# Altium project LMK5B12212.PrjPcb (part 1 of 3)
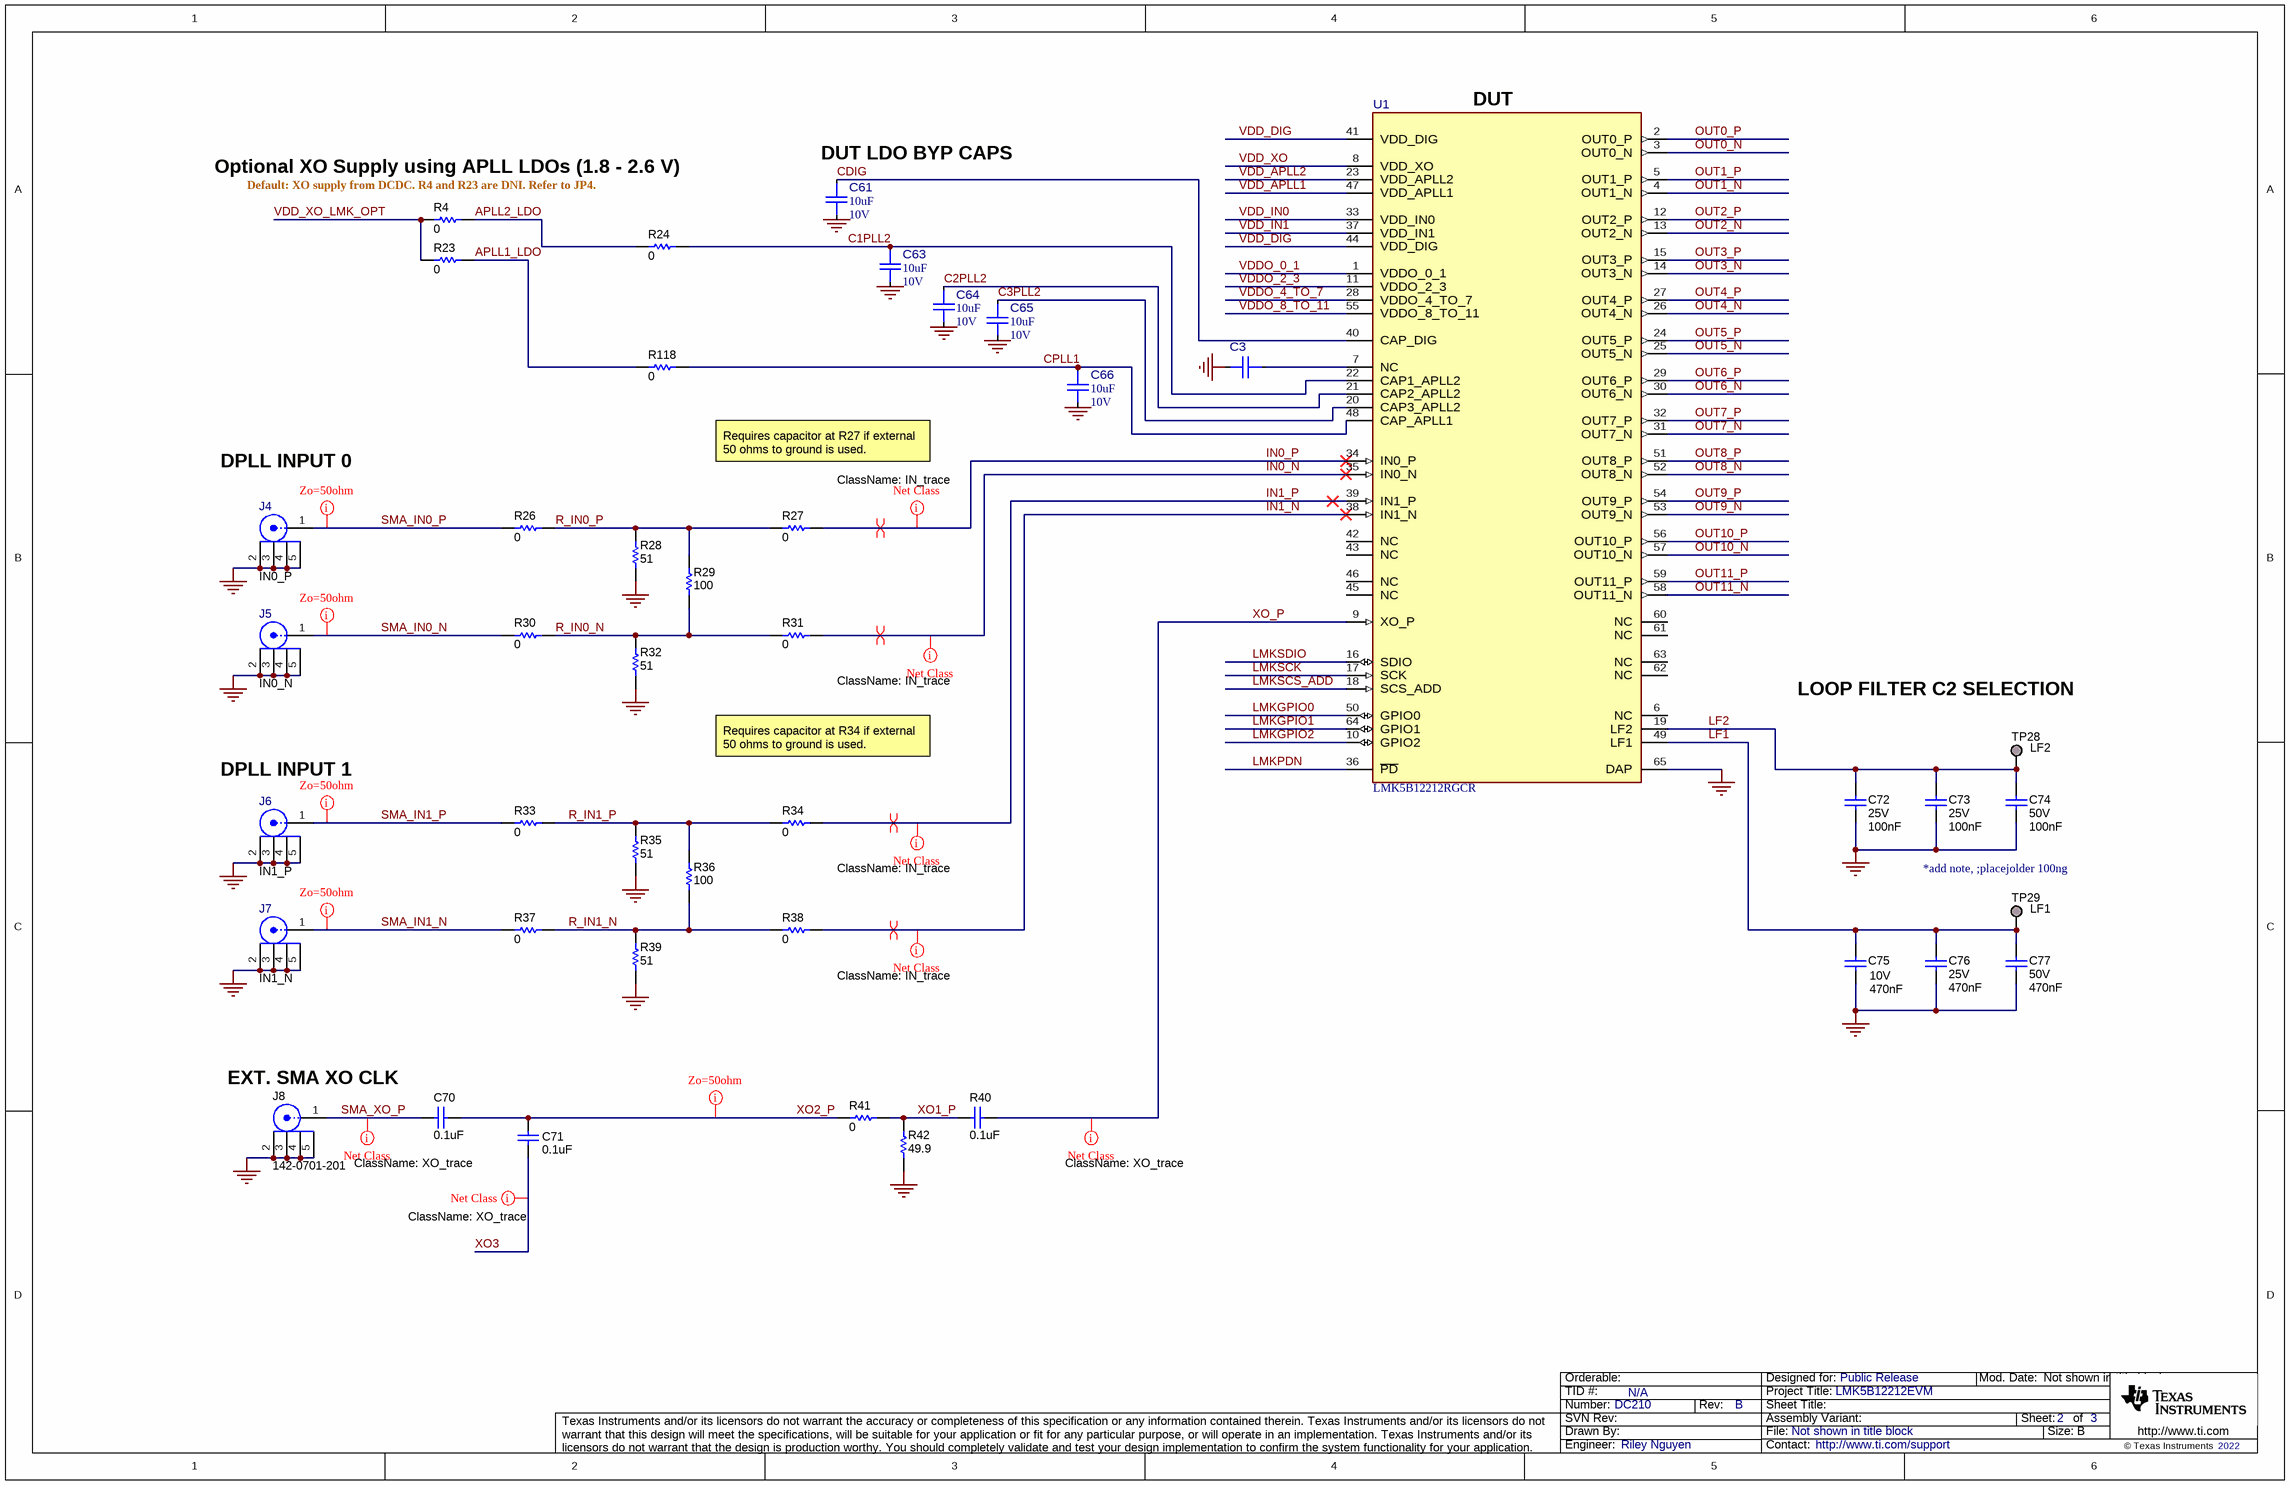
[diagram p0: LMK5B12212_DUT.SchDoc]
CopyrightYear: 2022; PCB_Rev: A; PRJ_Customer: Public Release; PRJ_Engineer: Riley Nguyen; PRJ_Number: DC210; PRJ_Title: LMK5B12212EVM; SCH_Rev: B; TechSupport: http://www.ti.com/support; TID: N/A
11 sheets, 474 parts. Net scope: global (net labels, ports and power ports of the same name join across sheets).
Board file: LMK5B12212_PCB.PcbDoc
Sheets:
  LMK5B12212_DUT.SchDoc
  LMK5B12212_Hardware.SchDoc
  LMK5B12212_Logic.SchDoc
  LMK5B12212_Outputs_A.SchDoc
  LMK5B12212_Outputs_B.SchDoc
  LMK5B12212_Outputs_C.SchDoc
  LMK5B12212_Power.SchDoc
  LMK5B12212_Power_Alternate.SchDoc
  LMK5B12212_PowerDist.SchDoc
  LMK5B12212_USB2ANY.SchDoc
  LMK5B12212_XO.SchDoc

## Sheet LMK5B12212_DUT.SchDoc
size 431 x 279 mm; Date: Not shown in title block; ApprovedBy: Not shown in title block; CheckedBy: Not shown in title block; Author: Not shown in title block; CompanyName: Not shown in title block; Engineer: Not shown in title block; Organization: Not shown in title block; Address1: Not shown in title block; Address2: Not shown in title block; Address3: Not shown in title block; Address4: Not shown in title block; DocumentNumber: 2; Revision: Use project parameter SCH_Rev; SheetNumber: 2; SheetTotal: 3; PageSetup: Record=PageOptions¦CenterHorizontal=True¦CenterVertical=True¦PrintScale=1.00¦XCorrection=1.00¦YCorrection=1.00¦PrintKind=0¦BorderSize=5000000¦LeftOffset=0¦BottomOffset=0¦Orientation=2¦PaperLength=1000¦PaperWidth=1000¦Scale=100¦PaperSource=15¦PrintQuality=600¦MediaType=1¦DitherType=10¦PaperKind=Letter¦PrintScaleMode=1

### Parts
C3  KGM05CR51A106MH  [FP-KGM05CR51A106MH_0402-MFG]  (value not drawn)
C61  ValueDisplayed: 10uF  VDC_V: 10V  [FP-KGM05CR51A106MH_0402-MFG]  (hidden comment: KGM05CR51A106MH)
C63  ValueDisplayed: 10uF  VDC_V: 10V  [FP-KGM05CR51A106MH_0402-MFG]  (hidden comment: KGM05CR51A106MH)
C64  ValueDisplayed: 10uF  VDC_V: 10V  [FP-KGM05CR51A106MH_0402-MFG]  (hidden comment: KGM05CR51A106MH)
C65  ValueDisplayed: 10uF  VDC_V: 10V  [FP-KGM05CR51A106MH_0402-MFG]  (hidden comment: KGM05CR51A106MH)
C66  ValueDisplayed: 10uF  VDC_V: 10V  [FP-KGM05CR51A106MH_0402-MFG]  (hidden comment: KGM05CR51A106MH)
C70  ValueDisplayed: 0.1uF  [0603S]  (hidden comment: C0603C104J3RACTU)
C71  ValueDisplayed: 0.1uF  [0603S]  (hidden comment: C0603C104J3RACTU)
C72  VDC_V: 25V  Cap_F: 100nF  [0603]  (hidden comment: C0603C104J3RACTU)
C73  VDC_V: 25V  ValueDisplayed: 100nF  [0805_150]  (hidden comment: Capacitor)
C74  VDC_V: 50V  ValueDisplayed: 100nF  [1210_280]  (hidden comment: C3225C0G1H104J250AA)
C75  Cap_F: 470nF  VDC_V: 10V  [0603]  (hidden comment: GRM188R71A474KA61D)
C76  VDC_V: 25V  ValueDisplayed: 470nF  [0805_150]  (hidden comment: Capacitor)
C77  VDC_V: 50V  ValueDisplayed: 470nF  [1210_280]  (hidden comment: C3225C0G1H104J250AA)
J4  IN0_P  [FP-CON-SMA-EDGE-S_CONN_JACK-MFG]
J5  IN0_N  [FP-CON-SMA-EDGE-S_CONN_JACK-MFG]
J6  IN1_P  [FP-CON-SMA-EDGE-S_CONN_JACK-MFG]
J7  IN1_N  [FP-CON-SMA-EDGE-S_CONN_JACK-MFG]
J8  142-0701-201  [Johnson_142-0701-20x]
R4  ValueDisplayed: 0  [0603]  (hidden comment: ERJ-3GEY0R00V)
R23  ValueDisplayed: 0  [0603]  (hidden comment: ERJ-3GEY0R00V)
R24  ValueDisplayed: 0  [0402L]  (hidden comment: CRCW04020000Z0EDHP)
R26  ValueDisplayed: 0  [0402L]  (hidden comment: CRCW04020000Z0EDHP)
R27  ValueDisplayed: 0  [0402L]  (hidden comment: CRCW04020000Z0EDHP)
R28  ValueDisplayed: 51  [0402S]  (hidden comment: RC0402JR-0751RL)
R29  ValueDisplayed: 100  [0603S]  (hidden comment: CRCW0603100RFKEA)
R30  ValueDisplayed: 0  [0402L]  (hidden comment: CRCW04020000Z0EDHP)
R31  ValueDisplayed: 0  [0402L]  (hidden comment: CRCW04020000Z0EDHP)
R32  ValueDisplayed: 51  [0402S]  (hidden comment: RC0402JR-0751RL)
R33  ValueDisplayed: 0  [0402L]  (hidden comment: CRCW04020000Z0EDHP)
R34  ValueDisplayed: 0  [0402L]  (hidden comment: CRCW04020000Z0EDHP)
R35  ValueDisplayed: 51  [0402S]  (hidden comment: RC0402JR-0751RL)
R36  ValueDisplayed: 100  [0603S]  (hidden comment: CRCW0603100RFKEA)
R37  ValueDisplayed: 0  [0402L]  (hidden comment: CRCW04020000Z0EDHP)
R38  ValueDisplayed: 0  [0402L]  (hidden comment: CRCW04020000Z0EDHP)
R39  ValueDisplayed: 51  [0402S]  (hidden comment: RC0402JR-0751RL)
R40  ValueDisplayed: 0.1uF  [0603S]  (hidden comment: Capacitor)
R41  value 0  [0603S]  (hidden comment: Resistor)
R42  ValueDisplayed: 49.9  [0603S]  (hidden comment: Resistor)
R118  ValueDisplayed: 0  [0402L]  (hidden comment: CRCW04020000Z0EDHP)
TP28  LF2  [TP_SM_1MM]  (no BOM)
TP29  LF1  [TP_SM_1MM]  (no BOM)
U1  LMK5B12212RGCR  [RGC0064E-MFG]

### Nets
GND: C3.2 C61.2 C63.2 C64.2 C65.2 C66.2 C72.2 C73.1 C74.2 C75.2 C76.1 C77.2 J4.2 J4.3 J4.4 J4.5 J5.2 J5.3 J5.4 J5.5 J6.2 J6.3 J6.4 J6.5 J7.2 J7.3 J7.4 J7.5 J8.2 J8.3 J8.4 J8.5 R28.1 R32.1 R35.1 R39.1 R42.1 U1.65(DAP)
APLL1_LDO: R23.2 R118.1
APLL2_LDO: R4.2 R24.1
C1PLL2: C63.1 R24.2 U1.22(CAP1_APLL2)
C2PLL2: C64.1 U1.21(CAP2_APLL2)
C3PLL2: C65.1 U1.20(CAP3_APLL2)
CDIG: C61.1 U1.40(CAP_DIG)
CPLL1: C66.1 R118.2 U1.48(CAP_APLL1)
IN0_N: R31.2 U1.35(IN0_N)
IN0_P: R27.2 U1.34(IN0_P)
IN1_N: R38.2 U1.38(IN1_N)
IN1_P: R34.2 U1.39(IN1_P)
LF1: C75.1 C76.2 C77.1 TP29.1 U1.49(LF1)
LF2: C72.1 C73.2 C74.1 TP28.1 U1.19(LF2)
LMKGPIO0: U1.50(GPIO0)
LMKGPIO1: U1.64(GPIO1)
LMKGPIO2: U1.10(GPIO2)
LMKPDN: U1.36(~{PD})
LMKSCK: U1.17(SCK)
LMKSCS_ADD: U1.18(SCS_ADD)
LMKSDIO: U1.16(SDIO)
OUT0_N: U1.3(OUT0_N)
OUT0_P: U1.2(OUT0_P)
OUT1_N: U1.4(OUT1_N)
OUT1_P: U1.5(OUT1_P)
OUT2_N: U1.13(OUT2_N)
OUT2_P: U1.12(OUT2_P)
OUT3_N: U1.14(OUT3_N)
OUT3_P: U1.15(OUT3_P)
OUT4_N: U1.26(OUT4_N)
OUT4_P: U1.27(OUT4_P)
OUT5_N: U1.25(OUT5_N)
OUT5_P: U1.24(OUT5_P)
OUT6_N: U1.30(OUT6_N)
OUT6_P: U1.29(OUT6_P)
OUT7_N: U1.31(OUT7_N)
OUT7_P: U1.32(OUT7_P)
OUT8_N: U1.52(OUT8_N)
OUT8_P: U1.51(OUT8_P)
OUT9_N: U1.53(OUT9_N)
OUT9_P: U1.54(OUT9_P)
OUT10_N: U1.57(OUT10_N)
OUT10_P: U1.56(OUT10_P)
OUT11_N: U1.58(OUT11_N)
OUT11_P: U1.59(OUT11_P)
R_IN0_N: R29.1 R30.2 R31.1 R32.2
R_IN0_P: R26.2 R27.1 R28.2 R29.2
R_IN1_N: R36.1 R37.2 R38.1 R39.2
R_IN1_P: R33.2 R34.1 R35.2 R36.2
SMA_IN0_N: J5.1 R30.1
SMA_IN0_P: J4.1 R26.1
SMA_IN1_N: J7.1 R37.1
SMA_IN1_P: J6.1 R33.1
SMA_XO_P: C70.1 J8.1
VDD_APLL1: U1.47(VDD_APLL1)
VDD_APLL2: U1.23(VDD_APLL2)
VDD_DIG: U1.41(VDD_DIG) U1.44(VDD_DIG)
VDD_IN0: U1.33(VDD_IN0)
VDD_IN1: U1.37(VDD_IN1)
VDD_XO: U1.8(VDD_XO)
VDD_XO_LMK_OPT: R4.1 R23.1
VDDO_0_1: U1.1(VDDO_0_1)
VDDO_2_3: U1.11(VDDO_2_3)
VDDO_4_TO_7: U1.28(VDDO_4_TO_7)
VDDO_8_TO_11: U1.55(VDDO_8_TO_11)
XO1_P: R40.1 R41.2 R42.2
XO2_P: C70.2 C71.1 R41.1
XO3: C71.2
XO_P: R40.2 U1.9(XO_P)
NetC3_1: C3.1 U1.7(NC)

Not connected (* = marked no-connect by the designer): U1 6(NC) 42(NC) 43(NC) 45(NC) 46(NC) 60(NC) 61(NC) 62(NC) 63(NC)

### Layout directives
rule Impedance Constraint [Min = 45.00    Max = 55.00    ]: SMA_IN0_N, SMA_IN0_P, SMA_IN1_N, SMA_IN1_P, XO2_P
differential pair: IN0_N, IN0_P, IN1_N, IN1_P
net class XO_trace: SMA_XO_P, XO3, XO_P
net class IN_trace: IN0_N, IN0_P, IN1_N, IN1_P

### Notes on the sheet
- (near U1) DUT
- (near R4) Optional XO Supply using APLL LDOs (1.8 - 2.6 V)
- (near C61) DUT LDO BYP CAPS
- (near R4) Default: XO supply from DCDC. R4 and R23 are DNI. Refer to JP4.
- DPLL INPUT 0
- Requires capacitor at R27 if external 50 ohms to ground is used.
- LOOP FILTER C2 SELECTION
- (near J6) DPLL INPUT 1
- Requires capacitor at R34 if external 50 ohms to ground is used.
- *add note, ;placejolder 100ng
- (near J8) EXT. SMA XO CLK

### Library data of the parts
C3 = CMP-0043010-1: 10 µF ±20% 10V Ceramic Capacitor X5R 0402 (1005 Metric); Manufacturer: KYOCERA AVX; AEC Qualified: No; Cap_F: 10µF; SizeZ_mm: 0.7mm; TempCo: 15%; ValueDisplayed: 10uF; Value: 10µF
C61 C63-C66 = CMP-0043010-1: 10 µF ±20% 10V Ceramic Capacitor X5R 0402 (1005 Metric); Manufacturer: KYOCERA AVX; AEC Qualified: No; Cap_F: 10µF; SizeZ_mm: 0.7mm; TempCo: 15%; Value: 10µF
C70 C71 = CMP-0006856-6: CAP, CERM, 0.1 uF, 25 V, +/- 5%, X7R, 0603; Manufacturer: Kemet; TaMin_C: -55°C; Polarized: N; SizeAreaWB_mm2: 4.68; Value1: Unknown; U/M: EA; Value: 0.1uF; TaMax_C: 125°C; SizeZ_mm: 1; SizeX_mm: 1.6; SizeY_mm: 0.8; Cap_Case: 0603; Value2: 25V; SizeArea_mm2: 1.28; Cap_F: 100nF; AEC Category: Q200
C72 = CMP-0006856-6: CAP, CERM, 0.1 uF, 25 V, +/- 5%, X7R, 0603; Manufacturer: Kemet; Polarized: N; TaMax_C: 125°C; TaMin_C: -55°C; Value: 0.1uF; Value1: Unknown; U/M: EA; AEC Category: Q200; SizeArea_mm2: 1.28; SizeAreaWB_mm2: 4.68; SizeX_mm: 1.6; SizeY_mm: 0.8; SizeZ_mm: 1
C73 C76 = CMP-0078743-1: CAP, CERM, 0.047 µF, 25 V,+/- 5%, C0G/NP0, AEC-Q200 Grade 1, 0805; Manufacturer: Kemet; PartNumber: C0805C473J3GACTU; Polarized: N; TaMax_C: 125°C; TaMin_C: -55°C; Cap_F: 47nF; Value: 0.047uF; U/M: EA; SizeArea_mm2: 2.5; SizeAreaWB_mm2: 6.75; SizeX_mm: 2; SizeY_mm: 1.25; SizeZ_mm: 1.5; AEC Category: Q200; AEC Qualified: Y; AEC Grade: 1; Green_REACh: Incomplete; Green_Lifecycle: Not Set
C74 = CMP-0081101-1: CAP, CERM, 0.1 µF, 50 V,+/- 5%, C0G/NP0, 1210; Manufacturer: TDK; TaMin_C: -55°C; Polarized: N; SizeAreaWB_mm2: 14.7; U/M: EA; Value: 0.1uF; TaMax_C: 125°C; SizeZ_mm: 2.8; SizeX_mm: 3.2; SizeY_mm: 2.5; Cap_Case: 1210; SizeArea_mm2: 8; AEC Category: Q200; Green_Lifecycle: Active; Green_REACh: Incomplete
C75 = CMP-0007373-4: CAP, CERM, 0.47 uF, 10 V, +/- 10%, X7R, 0603; Manufacturer: MuRata; Polarized: N; Value: 0.47uF; U/M: EA; Value1: Unknown; TaMin_C: -55°C; TaMax_C: 125°C; SizeArea_mm2: 1.28; SizeAreaWB_mm2: 4.68; SizeX_mm: 1.6; SizeY_mm: 0.8; SizeZ_mm: 1; AEC Category: Q200
C77 = CMP-0081101-1: CAP, CERM, 0.1 µF, 50 V,+/- 5%, C0G/NP0, 1210; Manufacturer: TDK; TaMin_C: -55°C; Polarized: N; SizeAreaWB_mm2: 14.7; U/M: EA; Value: 0.1uF; TaMax_C: 125°C; SizeZ_mm: 2.8; SizeX_mm: 3.2; SizeY_mm: 2.5; Cap_Case: 1210; SizeArea_mm2: 8; Cap_F: 100nF; AEC Category: Q200; Green_Lifecycle: Active; Green_REACh: Incomplete
J4-J7 = CMP-0088000-4: CONN SMA JACK STR EDGE MNT; Manufacturer: RF Solutions Ltd.; PartNumber: CON-SMA-EDGE-S; ContactFinish: Gold; Shrouded: true
J8 = CMP-0055819-1: Connector, SMA, TH; Manufacturer: Cinch Connectivity; CNHeader: FALSE; CT: TRUE; Green_Lifecycle: Not Set; Green_REACh: Incomplete
R4 R23 = CMP-0025874-4: RES, 0, 5%, 0.1 W, AEC-Q200 Grade 0, 0603; Manufacturer: Panasonic; CompType: Resistor; VDC_V: 50V; Power_W: 100mW; Value: 0; Value_Code: 0000; Value2: 0.1W; EIA_Code: E24; TempCo: 600 ppm/C; AEC Category: Q200; AEC Qualified: Y; SizeArea_mm2: 1.28; SizeX_mm: 1.6; SizeY_mm: 0.8; SizeZ_mm: 1; SizeAreaWB_mm2: 4.68
R24 R26 R30 R31 R33 R34 R37 R38 R118 = CMP-0081856-1: RES, 0, 0%, 0.2 W, AEC-Q200 Grade 0, 0402; Manufacturer: Vishay-Dale; VDC_V: 50V; Power_W: 200mW; Value: 0; Value2: 0.2W; AEC Category: Q200; AEC Qualified: Y; SizeArea_mm2: 0.5; SizeX_mm: 1; SizeZ_mm: 0.6; SizeAreaWB_mm2: 3
R27 = CMP-0081856-1: RES, 0, 0%, 0.2 W, AEC-Q200 Grade 0, 0402; Manufacturer: Vishay-Dale; CompType: Resistor; VDC_V: 50V; Power_W: 200mW; Value: 0; Value2: 0.2W; AEC Category: Q200; AEC Qualified: Y; SizeArea_mm2: 0.5; SizeX_mm: 1; SizeZ_mm: 0.6; SizeAreaWB_mm2: 3
R28 R32 R35 R39 = CMP-0027006-2: RES, 51, 5%, 0.0625 W, 0402; Manufacturer: Yageo America; Value: 51; Value_Code: 51R0; Power_W: 62.5mW; VDC_V: 50V; TempCo: 100 ppm/C; EIA_Code: E24; AEC Category: Q200; AEC Qualified: N; SizeArea_mm2: 0.5; SizeX_mm: 1; SizeZ_mm: 0.6; U/M: EA
R29 R36 = CMP-0021991-4: RES, 100, 1%, 0.1 W, AEC-Q200 Grade 0, 0603; Manufacturer: Vishay-Dale; Value: 100; Value_Code: 100R; Power_W: 100mW; Value2: 0.1W; VDC_V: 75V; TempCo: 100 ppm/C; EIA_Code: E96; AEC Category: Q200; AEC Qualified: Y; AEC Grade: 0; SizeArea_mm2: 1.28; SizeX_mm: 1.6; SizeY_mm: 0.8; SizeZ_mm: 1
R40 = CMP-0006856-6: CAP, CERM, 0.1 uF, 25 V, +/- 5%, X7R, 0603; Manufacturer: Kemet; PartNumber: C0603C104J3RACTU; VDC_V: 25V; Value: 0.1uF; Value1: Unknown; U/M: EA; Polarized: N; Cap_F: 100nF; TaMin_C: -55°C; TaMax_C: 125°C; Cap_Case: 0603; SizeArea_mm2: 1.28; SizeAreaWB_mm2: 4.68; SizeX_mm: 1.6; SizeY_mm: 0.8; SizeZ_mm: 1; AEC Category: Q200
R41 = CMP-0025697-4: RES, 0, 5%, 0.1 W, AEC-Q200 Grade 0, 0603; Manufacturer: Vishay-Dale; PartNumber: CRCW06030000Z0EA; VDC_V: 75V; Power_W: 100mW; Value_Code: 0000; Value2: 0.1W; EIA_Code: E24; TempCo: 200 ppm/C; AEC Category: Q200; AEC Qualified: Y; SizeArea_mm2: 1.28; SizeX_mm: 1.6; SizeY_mm: 0.8; SizeZ_mm: 1
R42 = CMP-0022448-4: RES, 49.9, 1%, 0.1 W, AEC-Q200 Grade 0, 0603; PartNumber: CRCW060349R9FKEA; Manufacturer: Vishay-Dale; Value: 49.9; Value_Code: 49R9; Power_W: 100mW; Value2: 0.1W; VDC_V: 75V; TempCo: 100 ppm/C; EIA_Code: E96; AEC Category: Q200; AEC Qualified: Y; AEC Grade: 0; SizeArea_mm2: 1.28; SizeX_mm: 1.6; SizeY_mm: 0.8; SizeZ_mm: 1
TP28 TP29 = CMP-0003825-1: 1mm Test Point, SMT; Manufacturer: Any
U1 = CMP-0096725-1: 1-DPLL 2-APLL 2-IN 12-OUT Network Synchronizer with JESD204B/C and BAW for Wired Communications; Manufacturer: Texas Instruments; Part Number: LMK5C22212RGCR; AEC Qualified: No; Max Supply Voltage: 3.465V; Number Of Outputs: 12; Interface: I2C,SPI; Max Frequency: 800MHz; TJmax_C: +125°C; SizeZ_mm: 1mm; Pll: YES; Standoff Height: 0mm; Min Supply Voltage: 3.135V

## Sheet LMK5B12212_Hardware.SchDoc
size 431 x 279 mm; Date: Not shown in title block; ApprovedBy: Not shown in title block; CheckedBy: Not shown in title block; Author: Not shown in title block; CompanyName: Not shown in title block; Engineer: Not shown in title block; Organization: Not shown in title block; Address1: Not shown in title block; Address2: Not shown in title block; Address3: Not shown in title block; Address4: Not shown in title block; DocumentNumber: 3; Revision: Use project parameter SCH_Rev; SheetNumber: 3; SheetTotal: 3; PageSetup: Record=PageOptions¦CenterHorizontal=True¦CenterVertical=True¦PrintScale=1.00¦XCorrection=1.00¦YCorrection=1.00¦PrintKind=0¦BorderSize=5000000¦LeftOffset=0¦BottomOffset=0¦Orientation=2¦PaperLength=1000¦PaperWidth=1000¦Scale=100¦PaperSource=15¦PrintQuality=600¦MediaType=1¦DitherType=10¦PaperKind=Letter¦PrintScaleMode=1
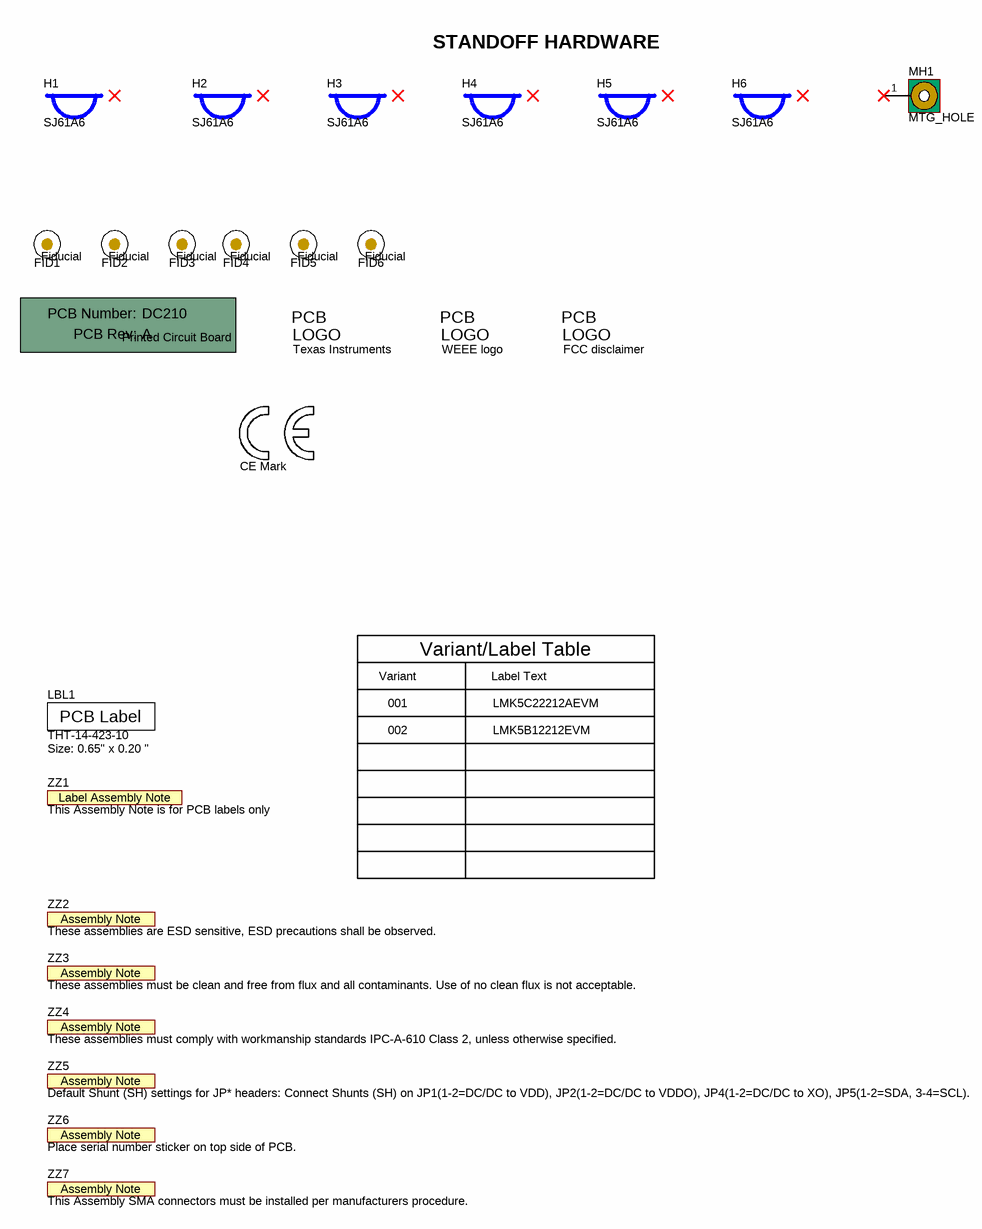
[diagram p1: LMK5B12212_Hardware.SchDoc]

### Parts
!PCB1  Printed Circuit Board  (mechanical)
FID1  Fiducial  [Fiducial10-20]
FID2  Fiducial  [Fiducial10-20]
FID3  Fiducial  [Fiducial10-20]
FID4  Fiducial  [Fiducial10-20]
FID5  Fiducial  [Fiducial10-20]
FID6  Fiducial  [Fiducial10-20]
H1  SJ61A6  [3M_SJ61A6]
H2  SJ61A6  [3M_SJ61A6]
H3  SJ61A6  [3M_SJ61A6]
H4  SJ61A6  [3M_SJ61A6]
H5  SJ61A6  [3M_SJ61A6]
H6  SJ61A6  [3M_SJ61A6]
LBL1  THT-14-423-10  Note: Size: 0.65" x 0.20 "  [Label_650x200]
Logo1  Texas Instruments  [TI_Stacked_Overlay_Medium]  (no BOM)
Logo2  FCC disclaimer  [FCC_disclaimer]  (no BOM)
Logo3  CE Mark  [CE_Mark_5mm]  (no BOM)
Logo4  WEEE logo  [WEEE_Minimum]  (no BOM)
MH1  MTG_HOLE  [MTGP_252mil_157mil_6Via]  (no BOM)
ZZ1  This Assembly Note is for PCB labels only  [AssemblyNoteLabel]  (no BOM)
ZZ2  These assemblies are ESD sensitive, ESD precautions shall be observed.  [AssemblyNote]  (no BOM)
ZZ3  These assemblies must be clean and free from flux and all contaminants. Use of no clean flux is not acceptable.  [AssemblyNote]  (no BOM)
ZZ4  These assemblies must comply with workmanship standards IPC-A-610 Class 2, unless otherwise specified.  [AssemblyNote]  (no BOM)
ZZ5  Default Shunt (SH) settings for JP* headers: Connect Shunts (SH) on JP1(1-2=DC/DC to VDD), JP2(1-2=DC/DC to VDDO), JP4(1-2=DC/DC to XO), JP5(1-2=SDA, 3-4=SCL).  [AssemblyNote]  (no BOM)
ZZ6  Place serial number sticker on top side of PCB.  [AssemblyNote]  (no BOM)
ZZ7  This Assembly SMA connectors must be installed per manufacturers procedure.  [AssemblyNote]  (no BOM)

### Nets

Not connected (* = marked no-connect by the designer): MH1 1*

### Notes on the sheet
- STANDOFF HARDWARE
- Variant
- Variant/Label Table
- Label Text
- 001
- 002
- LMK5C22212AEVM
- LMK5B12212EVM

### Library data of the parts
!PCB1 = CMP-0003618-2: Manufacturer: Any; PartNumber: DC210
FID1-FID6 = CMP-0077181-1: Fiducial mark.  There is nothing to buy or mount.
H1-H6 = CMP-0079645-1: BUMPER CYLIN 0.312" DIA; Manufacturer: 3M; Green_Lifecycle: Not Set; Green_REACh: Incomplete
LBL1 = CMP-0003625-1: Thermal Transfer Printable Labels, 0.650" W x 0.200" H - 10,000 per roll; Manufacturer: Brady
Logo1 = CMP-0074838-1: Texas Instrument Corporate Signature; SymbolCreator: a0412235; Lib Reference: TI_Logo
Logo2 = CMP-0074847-1: FCC_disclaimer
Logo3 = CMP-0074844-1: SymbolCreator: a0412235
Logo4 = CMP-0074769-1
MH1 = CMP-0078422-2: PCB Mounting Hole; Manufacturer: Any; Key: Mounting Hole (non-standard)
ZZ1 = CMP-0003616-3
ZZ2 = CMP-0077236-1
ZZ3 = CMP-0077237-1
ZZ4 = CMP-0077238-1
ZZ5-ZZ7 = CMP-0003615-1: This Assembly Note will show in the PcbDoc and associated outputs

## Sheet LMK5B12212_Logic.SchDoc
size 431 x 279 mm; Date: Not shown in title block; ApprovedBy: Not shown in title block; CheckedBy: Not shown in title block; Author: Not shown in title block; CompanyName: Not shown in title block; Engineer: Not shown in title block; Organization: Not shown in title block; Address1: Not shown in title block; Address2: Not shown in title block; Address3: Not shown in title block; Address4: Not shown in title block; DocumentNumber: 2; Revision: Use project parameter SCH_Rev; SheetNumber: 2; SheetTotal: 3; PageSetup: Record=PageOptions¦CenterHorizontal=True¦CenterVertical=True¦PrintScale=1.00¦XCorrection=1.00¦YCorrection=1.00¦PrintKind=0¦BorderSize=5000000¦LeftOffset=0¦BottomOffset=0¦Orientation=2¦PaperLength=1000¦PaperWidth=1000¦Scale=100¦PaperSource=15¦PrintQuality=600¦MediaType=1¦DitherType=10¦PaperKind=Letter¦PrintScaleMode=1
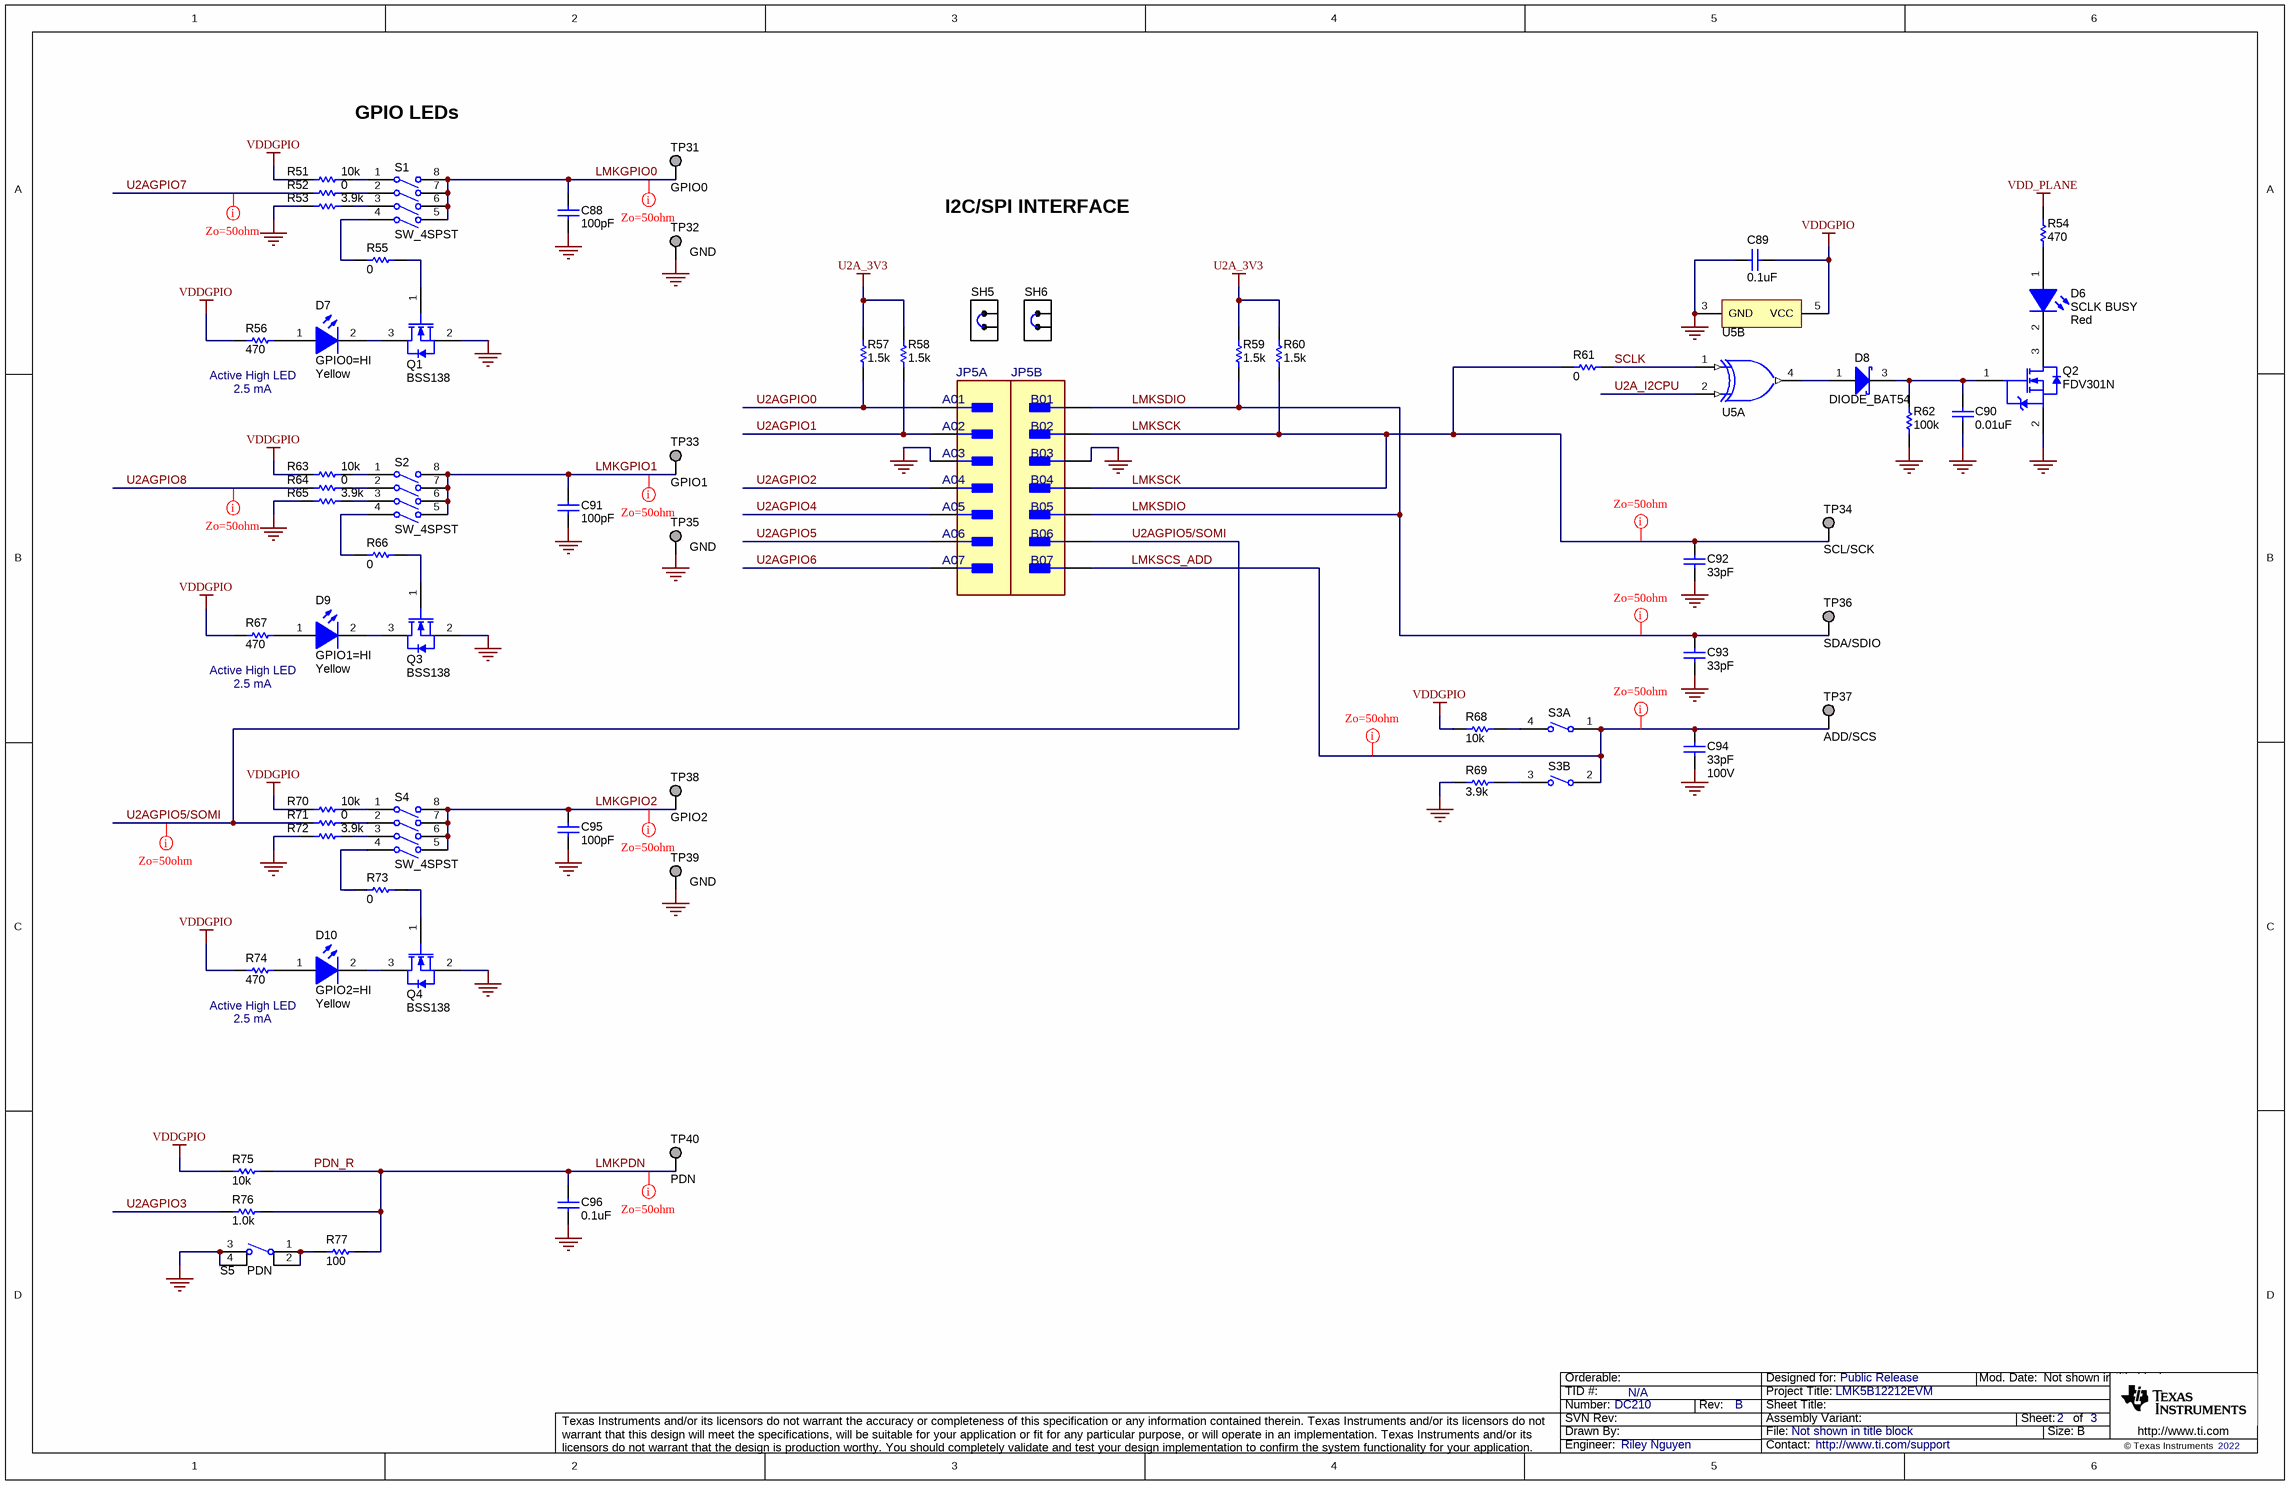
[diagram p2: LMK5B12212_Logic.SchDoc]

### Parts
C88  ValueDisplayed: 100pF  [0603]  (hidden comment: Capacitor)
C89  ValueDisplayed: 0.1uF  [0603]  (hidden comment: Capacitor)
C90  ValueDisplayed: 0.01uF  [0603]  (hidden comment: Capacitor)
C91  ValueDisplayed: 100pF  [0603]  (hidden comment: Capacitor)
C92  ValueDisplayed: 33pF  [0603]  (hidden comment: Capacitor)
C93  ValueDisplayed: 33pF  [0603]  (hidden comment: Capacitor)
C94  ValueDisplayed: 33pF  VDC_V: 100V  [0603]  (hidden comment: 06031A330JAT2A)
C95  ValueDisplayed: 100pF  [0603]  (hidden comment: Capacitor)
C96  ValueDisplayed: 0.1uF  [0603]  (hidden comment: C0603C104J3RACTU)
D6  SCLK BUSY  value Red  [LED_LTST-C170_Red]
D7  GPIO0=HI  value Yellow  [LED_LTST-C170]
D8  DIODE_BAT54  [SOT-23]
D9  GPIO1=HI  value Yellow  [LED_LTST-C170]
D10  GPIO2=HI  value Yellow  [LED_LTST-C170]
JP5  54202-G0807LF  [FP-54202-G0807LF_HDR14-MFG]  (value not drawn)  (parts A,B of 2)
Q1  BSS138  [SOT-23]
Q2  FDV301N  [SOT-23]
Q3  BSS138  [SOT-23]
Q4  BSS138  [SOT-23]
R51  ValueDisplayed: 10k  [0603]  (hidden comment: Resistor)
R52  ValueDisplayed: 0  [0603]  (hidden comment: Resistor)
R53  ValueDisplayed: 3.9k  [0603]  (hidden comment: CRCW06033K90JNEA)
R54  ValueDisplayed: 470  [0603]  (hidden comment: Resistor)
R55  ValueDisplayed: 0  [0603L]  (hidden comment: Resistor)
R56  ValueDisplayed: 470  [0603]  (hidden comment: Resistor)
R57  ValueDisplayed: 1.5k  [0603]  (hidden comment: Resistor)
R58  ValueDisplayed: 1.5k  [0603]  (hidden comment: Resistor)
R59  ValueDisplayed: 1.5k  [0603]  (hidden comment: Resistor)
R60  ValueDisplayed: 1.5k  [0603]  (hidden comment: Resistor)
R61  ValueDisplayed: 0  [0603]  (hidden comment: Resistor)
R62  ValueDisplayed: 100k  [0603]  (hidden comment: Resistor)
R63  ValueDisplayed: 10k  [0603]  (hidden comment: Resistor)
R64  ValueDisplayed: 0  [0603]  (hidden comment: Resistor)
R65  ValueDisplayed: 3.9k  [0603]  (hidden comment: CRCW06033K90JNEA)
R66  ValueDisplayed: 0  [0603L]  (hidden comment: Resistor)
R67  ValueDisplayed: 470  [0603]  (hidden comment: Resistor)
R68  ValueDisplayed: 10k  [0603]  (hidden comment: Resistor)
R69  ValueDisplayed: 3.9k  [0603]  (hidden comment: Resistor)
R70  ValueDisplayed: 10k  [0603]  (hidden comment: Resistor)
R71  ValueDisplayed: 0  [0603]  (hidden comment: Resistor)
R72  ValueDisplayed: 3.9k  [0603]  (hidden comment: CRCW06033K90JNEA)
R73  ValueDisplayed: 0  [0603L]  (hidden comment: Resistor)
R74  ValueDisplayed: 470  [0603]  (hidden comment: Resistor)
R75  ValueDisplayed: 10k  [0603]  (hidden comment: Resistor)
R76  ValueDisplayed: 1.0k  [0603]  (hidden comment: Resistor)
R77  ValueDisplayed: 100  [0603]  (hidden comment: ESR03EZPJ101)
S1  SW_4SPST  [SW_219-4LPST]
S2  SW_4SPST  [SW_219-4LPST]
S3  SW_219-2LPST  [SW_219-2LPST]  (value not drawn)  (parts A,B of 2)
S4  SW_4SPST  [SW_219-4LPST]
S5  PDN  [SW_FSM4JSMA]
SH5  SNT-100-BK-G  [SNT-100-BK-G]  (value not drawn)
SH6  SNT-100-BK-G  [SNT-100-BK-G]  (value not drawn)
TP31  GPIO0  [Keystone_5019]
TP32  GND  [Keystone_5019]
TP33  GPIO1  [Keystone_5019]
TP34  SCL/SCK  [Keystone_5019]
TP35  GND  [Keystone_5019]
TP36  SDA/SDIO  [Keystone_5019]
TP37  ADD/SCS  [Keystone_5019]
TP38  GPIO2  [Keystone_5019]
TP39  GND  [Keystone_5019]
TP40  PDN  [Keystone_5019]
U5  TI-XOR-1-2IN-5  [DBV0005A_N]  (value not drawn)  (parts A,B of 2)

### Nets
GND: C88.2 C89.1 C90.2 C91.2 C92.2 C93.2 C94.2 C95.2 C96.2 JP5.A03 JP5.B03 Q1.2(S) Q2.2(S) Q3.2(S) Q4.2(S) R53.1 R62.1 R65.1 R69.1 R72.1 S5.3 S5.4 TP32.1 TP35.1 TP39.1 U5.3(GND)
U2A_3V3: R57.2 R58.2 R59.2 R60.2
VDD_PLANE: R54.2
VDDGPIO: C89.2 R51.1 R56.2 R63.1 R67.2 R68.1 R70.1 R74.2 R75.1 U5.5(VCC)
LMKGPIO0: C88.1 S1.5(B4) S1.6(B3) S1.7(B2) S1.8(B1) TP31.1
LMKGPIO1: C91.1 S2.5(B4) S2.6(B3) S2.7(B2) S2.8(B1) TP33.1
LMKGPIO2: C95.1 S4.5(B4) S4.6(B3) S4.7(B2) S4.8(B1) TP38.1
LMKPDN: C96.1 R75.2 R76.2 R77.1 TP40.1  [also labelled PDN_R]
LMKSCK: C92.1 JP5.B02 JP5.B04 R60.1 R61.1 TP34.1
LMKSCS_ADD: C94.1 JP5.B07 S3.1(1A) S3.2(2A) TP37.1
LMKSDIO: C93.1 JP5.B01 JP5.B05 R59.1 TP36.1
SCLK: R61.2 U5.1(A)
U2A_I2CPU: U5.2(B)
U2AGPIO0: JP5.A01 R57.1
U2AGPIO1: JP5.A02 R58.1
U2AGPIO2: JP5.A04
U2AGPIO3: R76.1
U2AGPIO4: JP5.A05
U2AGPIO5: JP5.A06
U2AGPIO5/SOMI: JP5.B06 R71.2
U2AGPIO6: JP5.A07
U2AGPIO7: R52.1
U2AGPIO8: R64.1
NetC90_1: C90.1 D8.3(K) Q2.1(G) R62.2
NetD6_1: D6.1(A) R54.1
NetD6_2: D6.2(K) Q2.3(D)
NetD7_1: D7.1(A) R56.1
NetD7_2: D7.2(K) Q1.3(D)
NetD8_1: D8.1(A) U5.4(Y)
NetD9_1: D9.1(A) R67.1
NetD9_2: D9.2(K) Q3.3(D)
NetD10_1: D10.1(A) R74.1
NetD10_2: D10.2(K) Q4.3(D)
NetQ1_1: Q1.1(G) R55.2
NetQ3_1: Q3.1(G) R66.2
NetQ4_1: Q4.1(G) R73.2
NetR51_2: R51.2 S1.1(A1)
NetR52_2: R52.2 S1.2(A2)
NetR53_2: R53.2 S1.3(A3)
NetR55_1: R55.1 S1.4(A4)
NetR63_2: R63.2 S2.1(A1)
NetR64_2: R64.2 S2.2(A2)
NetR65_2: R65.2 S2.3(A3)
NetR66_1: R66.1 S2.4(A4)
NetR68_2: R68.2 S3.4(1B)
NetR69_2: R69.2 S3.3(2B)
NetR70_2: R70.2 S4.1(A1)
NetR71_1: R71.1 S4.2(A2)
NetR72_2: R72.2 S4.3(A3)
NetR73_1: R73.1 S4.4(A4)
NetR77_2: R77.2 S5.1 S5.2

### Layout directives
rule Impedance Constraint [Min = 45.00    Max = 55.00    ]: LMKGPIO0, LMKGPIO1, LMKGPIO2, LMKPDN, LMKSCK, LMKSCS_ADD, LMKSDIO, U2AGPIO5/SOMI, U2AGPIO7, U2AGPIO8

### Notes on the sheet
- GPIO LEDs
- I2C/SPI INTERFACE
- Active High LED
  2.5 mA

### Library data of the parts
C88 C91 C95 = CMP-0006763-4: CAP, CERM, 100 pF, 50 V, +/- 5%, C0G/NP0, 0603; PartNumber: 06035A101JAT2A; Manufacturer: AVX; Polarized: N; Value: 100pF; U/M: EA; ESR_ohm: 1.19d; Value1: 0.119 ohm; VDC_V: 50V; TaMin_C: -55°C; TaMax_C: 125°C; AEC Category: Q200; SizeArea_mm2: 1.28; SizeAreaWB_mm2: 4.68; SizeX_mm: 1.6; SizeY_mm: 0.8; SizeZ_mm: 1
C89 = CMP-0006857-4: CAP, CERM, 0.1 uF, 16 V, +/- 5%, X7R, 0603; PartNumber: C0603C104J4RACTU; Manufacturer: Kemet; Polarized: N; Value: 0.1uF; U/M: EA; Cap_F: 100nF; Value1: Unknown; VDC_V: 16V; TaMin_C: -55°C; TaMax_C: 125°C; AEC Category: Q200; SizeArea_mm2: 1.28; SizeAreaWB_mm2: 4.68; SizeX_mm: 1.6; SizeY_mm: 0.8; SizeZ_mm: 1
C90 = CMP-0006850-4: CAP, CERM, 0.01 uF, 50 V, +/- 5%, X7R, 0603; PartNumber: C0603C103J5RACTU; Manufacturer: Kemet; Polarized: N; Value: 0.01uF; U/M: EA; Cap_F: 10nF; Value1: Unknown; VDC_V: 50V; TaMin_C: -55°C; TaMax_C: 125°C; SizeArea_mm2: 1.28; SizeAreaWB_mm2: 4.68; SizeX_mm: 1.6; SizeY_mm: 0.8; SizeZ_mm: 1; AEC Category: Q200
C92 C93 = CMP-0006722-4: CAP, CERM, 33 pF, 100 V, +/- 5%, C0G/NP0, 0603; PartNumber: 06031A330JAT2A; Manufacturer: AVX; Polarized: N; Value: 33pF; U/M: EA; ESR_ohm: 2.09d; Value1: 0.209 ohm; VDC_V: 100V; TaMin_C: -55°C; TaMax_C: 125°C; AEC Category: Q200; SizeArea_mm2: 1.28; SizeAreaWB_mm2: 4.68; SizeX_mm: 1.6; SizeY_mm: 0.8; SizeZ_mm: 1
C94 = CMP-0006722-4: CAP, CERM, 33 pF, 100 V, +/- 5%, C0G/NP0, 0603; Manufacturer: AVX; Polarized: N; Value: 33pF; U/M: EA; ESR_ohm: 2.09d; Value1: 0.209 ohm; TaMin_C: -55°C; TaMax_C: 125°C; AEC Category: Q200; SizeArea_mm2: 1.28; SizeAreaWB_mm2: 4.68; SizeX_mm: 1.6; SizeY_mm: 0.8; SizeZ_mm: 1
C96 = CMP-0006856-6: CAP, CERM, 0.1 uF, 25 V, +/- 5%, X7R, 0603; Manufacturer: Kemet; Polarized: N; Value: 0.1uF; U/M: EA; Cap_F: 100nF; Value1: Unknown; VDC_V: 25V; TaMin_C: -55°C; TaMax_C: 125°C; AEC Category: Q200; SizeArea_mm2: 1.28; SizeAreaWB_mm2: 4.68; SizeX_mm: 1.6; SizeY_mm: 0.8; SizeZ_mm: 1
D6 = CMP-0002829-2: LED, Red, SMD; Manufacturer: Lite-On; PartNumber: LTST-C170KRKT; Type: AlInGaP; Vf_V: 2V; Io_A: 20mA; Value1: W; U/M: EA; SizeAreaWB_mm2: 6.75; SizeArea_mm2: 2.5; SizeX_mm: 2; SizeY_mm: 1.25; SizeZ_mm: 1.2
D7 D9 D10 = CMP-0002862-2: LED, Yellow , SMD; Manufacturer: Lite-On; PartNumber: LTST-C170KSKT; Type: AlInGaP; Vf_V: 2V; Io_A: 20mA; Value1: W; SizeArea_mm2: 2.5; SizeAreaWB_mm2: 6.75; SizeX_mm: 2; SizeY_mm: 1.25; SizeZ_mm: 1.2
D8 = CMP-0028451-2: Diode, Schottky, 30 V, 0.2 A, SOT-23; PartNumber: BAT54-7-F; Manufacturer: Diodes Inc.; Vf_V: 6.5dV; Value: 30V; Value1: 0.2A; Value2: 0.65V; Io_A: 2dA; TJmax_C: 125°C; SizeAreaWB_mm2: 14; SizeArea_mm2: 7.5; SizeX_mm: 2.5; SizeY_mm: 3; SizeZ_mm: 1.1; AEC Category: Q101; Green_Lifecycle: Active; Green_REACh: Passed
JP5 = CMP-0088459-1: Connector Header Surface Mount 14 position 0.100" (2.54mm); Manufacturer: Amphenol ICC; Standoff Height: 1.01mm; Voltage_V: 1.5kV; Conn Gender: Male; ContactFinish: Gold,Nickel; AEC Qualified: No; SizeZ_mm: 9.98mm; Conn Orientation: Straight; Current_A: 3A; Row_Count: 2
Q1 Q3 Q4 = CMP-0000755-1: MOSFET, N-CH, 50 V, 0.22 A, SOT-23; Manufacturer: Fairchild Semiconductor; Alternate Manufacturer: None; U/M: EA; ChType: N; Value: 50V; Rdson45_ohm: 6; Value2: 1.7 nC; QgTyp_nC: 1.7; Vgs_V: 20V; IdsMax_A: 2.2dA; AEC Category: Q101; SizeArea_mm2: 7.5; SizeAreaWB_mm2: 14; SizeX_mm: 2.5; SizeY_mm: 3; SizeZ_mm: 1.1
Q2 = CMP-0000281-1: MOSFET, N-CH, 25 V, 0.22 A, SOT-23; Manufacturer: Fairchild Semiconductor; Alternate Manufacturer: None; U/M: EA; ChType: N; Value: 25V; Rdson45_ohm: 4; Value2: 0.49 nC; QgTyp_nC: 0.49; Vgs_V: 8V; IdsMax_A: 2.2dA; SizeAreaWB_mm2: 14; SizeArea_mm2: 7.5; SizeX_mm: 2.5; SizeY_mm: 3; SizeZ_mm: 1.1; AEC Category: Q101
R51 R63 R68 R70 R75 = CMP-0025701-4: RES, 10 k, 5%, 0.1 W, AEC-Q200 Grade 0, 0603; PartNumber: CRCW060310K0JNEA; Manufacturer: Vishay-Dale; Value: 10k; Value_Code: 10k0; Power_W: 100mW; Value2: 0.1W; VDC_V: 75V; TempCo: 200 ppm/C; EIA_Code: E24; SizeArea_mm2: 1.28; SizeX_mm: 1.6; SizeY_mm: 0.8; SizeZ_mm: 1; AEC Category: Q200; AEC Qualified: Y; AEC Grade: 0
R52 R61 R64 R71 = CMP-0025697-4: RES, 0, 5%, 0.1 W, AEC-Q200 Grade 0, 0603; PartNumber: CRCW06030000Z0EA; Manufacturer: Vishay-Dale; Value: 0; Value_Code: 0000; Power_W: 100mW; Value2: 0.1W; VDC_V: 75V; TempCo: 200 ppm/C; EIA_Code: E24; AEC Category: Q200; AEC Qualified: Y; SizeArea_mm2: 1.28; SizeX_mm: 1.6; SizeY_mm: 0.8; SizeZ_mm: 1
R53 R65 R72 = CMP-0025799-4: RES, 3.9 k, 5%, 0.1 W, AEC-Q200 Grade 0, 0603; Manufacturer: Vishay-Dale; Value: 3.9k; Value_Code: 3k90; Power_W: 100mW; Value2: 0.1W; VDC_V: 75V; TempCo: 200 ppm/C; EIA_Code: E24; SizeArea_mm2: 1.28; SizeX_mm: 1.6; SizeY_mm: 0.8; SizeZ_mm: 1; AEC Category: Q200; AEC Qualified: Y; AEC Grade: 0
R54 R56 R67 R74 = CMP-0025813-4: RES, 470, 5%, 0.1 W, AEC-Q200 Grade 0, 0603; PartNumber: CRCW0603470RJNEA; Manufacturer: Vishay-Dale; Value: 470; Value_Code: 470R; Power_W: 100mW; Value2: 0.1W; VDC_V: 75V; TempCo: 200 ppm/C; EIA_Code: E24; SizeArea_mm2: 1.28; SizeX_mm: 1.6; SizeY_mm: 0.8; SizeZ_mm: 1; AEC Category: Q200; AEC Qualified: Y; AEC Grade: 0
R55 R66 R73 = CMP-0025697-4: RES, 0, 5%, 0.1 W, AEC-Q200 Grade 0, 0603; PartNumber: CRCW06030000Z0EA; Manufacturer: Vishay-Dale; Value: 0; Value_Code: 0000; Power_W: 100mW; Value2: 0.1W; VDC_V: 75V; TempCo: 200 ppm/C; EIA_Code: E24; SizeArea_mm2: 1.28; SizeX_mm: 1.6; SizeY_mm: 0.8; SizeZ_mm: 1; AEC Category: Q200; AEC Qualified: Y
R57-R60 = CMP-0025733-4: RES, 1.5 k, 5%, 0.1 W, AEC-Q200 Grade 0, 0603; PartNumber: CRCW06031K50JNEA; Manufacturer: Vishay-Dale; Value: 1.5k; Value_Code: 1k50; Power_W: 100mW; Value2: 0.1W; VDC_V: 75V; TempCo: 200 ppm/C; EIA_Code: E24; SizeArea_mm2: 1.28; SizeX_mm: 1.6; SizeY_mm: 0.8; SizeZ_mm: 1; AEC Category: Q200; AEC Qualified: Y; AEC Grade: 0
R62 = CMP-0025698-4: RES, 100 k, 5%, 0.1 W, AEC-Q200 Grade 0, 0603; PartNumber: CRCW0603100KJNEA; Manufacturer: Vishay-Dale; Value: 100k; Power_W: 100mW; Value2: 0.1W; VDC_V: 75V; TempCo: 200 ppm/C; EIA_Code: E24; SizeArea_mm2: 1.28; SizeX_mm: 1.6; SizeY_mm: 0.8; SizeZ_mm: 1; AEC Category: Q200; AEC Qualified: Y; AEC Grade: 0
R69 = CMP-0025799-4: RES, 3.9 k, 5%, 0.1 W, AEC-Q200 Grade 0, 0603; PartNumber: CRCW06033K90JNEA; Manufacturer: Vishay-Dale; Value: 3.9k; Value_Code: 3k90; Power_W: 100mW; Value2: 0.1W; VDC_V: 75V; TempCo: 200 ppm/C; EIA_Code: E24; SizeArea_mm2: 1.28; SizeX_mm: 1.6; SizeY_mm: 0.8; SizeZ_mm: 1; AEC Category: Q200; AEC Qualified: Y; AEC Grade: 0
R76 = CMP-0025729-4: RES, 1.0 k, 5%, 0.1 W, AEC-Q200 Grade 0, 0603; PartNumber: CRCW06031K00JNEA; Manufacturer: Vishay-Dale; Value: 1.0k; Res_ohm: 1k; Value_Code: 1k00; Power_W: 100mW; Value2: 0.1W; VDC_V: 75V; TempCo: 200 ppm/C; EIA_Code: E24; SizeArea_mm2: 1.28; SizeX_mm: 1.6; SizeY_mm: 0.8; SizeZ_mm: 1; AEC Category: Q200; AEC Qualified: Y; AEC Grade: 0
R77 = CMP-0025882-3: RES, 100, 5%, 0.25 W, AEC-Q200 Grade 0, 0603; Manufacturer: Rohm; Value: 100; Value_Code: 100R; Power_W: 250mW; Value2: 0.25W; VDC_V: 150V; TempCo: 200 ppm/C; EIA_Code: E24; SizeArea_mm2: 1.28; SizeX_mm: 1.6; SizeY_mm: 0.8; SizeZ_mm: 1; AEC Category: Q200; AEC Qualified: Y; AEC Grade: 0; U/M: EA
S1 S2 S4 = CMP-0002176-2: Switch, SPST 4 Pos, Top Actuated, SMT; PartNumber: 219-4LPST; Manufacturer: CTS Electrocomponents; VDC_V: 50V; SwitchFunction: Off-On; PositionCount: 4; CurrentRating_mA: 100A
S3 = CMP-0002127-2: Switch, Slide, SPST 2 poles, SMT; Manufacturer: CTS Electrocomponents; VDC_V: 20V; SwitchFunction: Off-On; PositionCount: 2; CurrentRating_mA: 100A
S5 = CMP-0002134-3: Switch, Tactile, SPST-NO, 0.05A, 12V, SMT; PartNumber: FSM4JSMA; Manufacturer: TE Connectivity; CurrentRating_mA: 50A; PositionCount: 1; SwitchFunction: Off-Mom
SH5 SH6 = CMP-0003623-3: Shunt, 100mil, Gold plated, Black; Manufacturer: Samtec; Alternate Manufacturer: 3M; Alternate PartNumber: 969102-0000-DA; Value: 1x2; Note: You can "mate" this to a header by matching the designator.  i.e. use SH-J3 for header J3
TP31-TP40 = CMP-0055162-1: Test Point, Miniature, SMT; Manufacturer: Keystone; PartNumber: 5019; CNHeader: FALSE; Green_Lifecycle: Active; Green_REACh: Passed; CT: TRUE
U5 = CMP-0052046-2: Single 2-Input Exclusive-OR Gate, DBV0005A (SOT-23-5); PartNumber: SN74LVC1G86DBVR; Manufacturer: Texas Instruments; Generic Part Number: SN74LVC1G86; SizeArea_mm2: 8.12; SizeAreaWB_mm2: 14.82; SizeX_mm: 2.8; SizeY_mm: 2.9; SizeZ_mm: 1.45; CompType: IC; 3-State Output: No; AEC Category: Q200; AEC Qualified: N; Bits(#): 1; F @ Nom Voltage(Max)(Mhz): 150; Gate Type: XOR; ICC @ Nom Voltage(Max)(mA): 0.01; Input Type: CMOS/TTL; Logic: True; Output Drive (IOL/IOH)(Max)(mA): 32/-32; Output Type: CMOS; Rating: Catalog; tpd @ Nom Voltage(Max)(ns): 9.9,5.5,5,4; VCC(Max)(V): 5.5; VCC(Min)(V): 1.65; Voltage(Nom)(V): 1.8,2.5,3.3,5

## Sheet LMK5B12212_Outputs_A.SchDoc
size 431 x 279 mm; Date: Not shown in title block; ApprovedBy: Not shown in title block; CheckedBy: Not shown in title block; Author: Not shown in title block; CompanyName: Not shown in title block; Engineer: Not shown in title block; Organization: Not shown in title block; Address1: Not shown in title block; Address2: Not shown in title block; Address3: Not shown in title block; Address4: Not shown in title block; DocumentNumber: 2; Revision: Use project parameter SCH_Rev; SheetNumber: 2; SheetTotal: 3; PageSetup: Record=PageOptions¦CenterHorizontal=True¦CenterVertical=True¦PrintScale=1.00¦XCorrection=1.00¦YCorrection=1.00¦PrintKind=0¦BorderSize=5000000¦LeftOffset=0¦BottomOffset=0¦Orientation=2¦PaperLength=1000¦PaperWidth=1000¦Scale=100¦PaperSource=15¦PrintQuality=600¦MediaType=1¦DitherType=10¦PaperKind=Letter¦PrintScaleMode=1
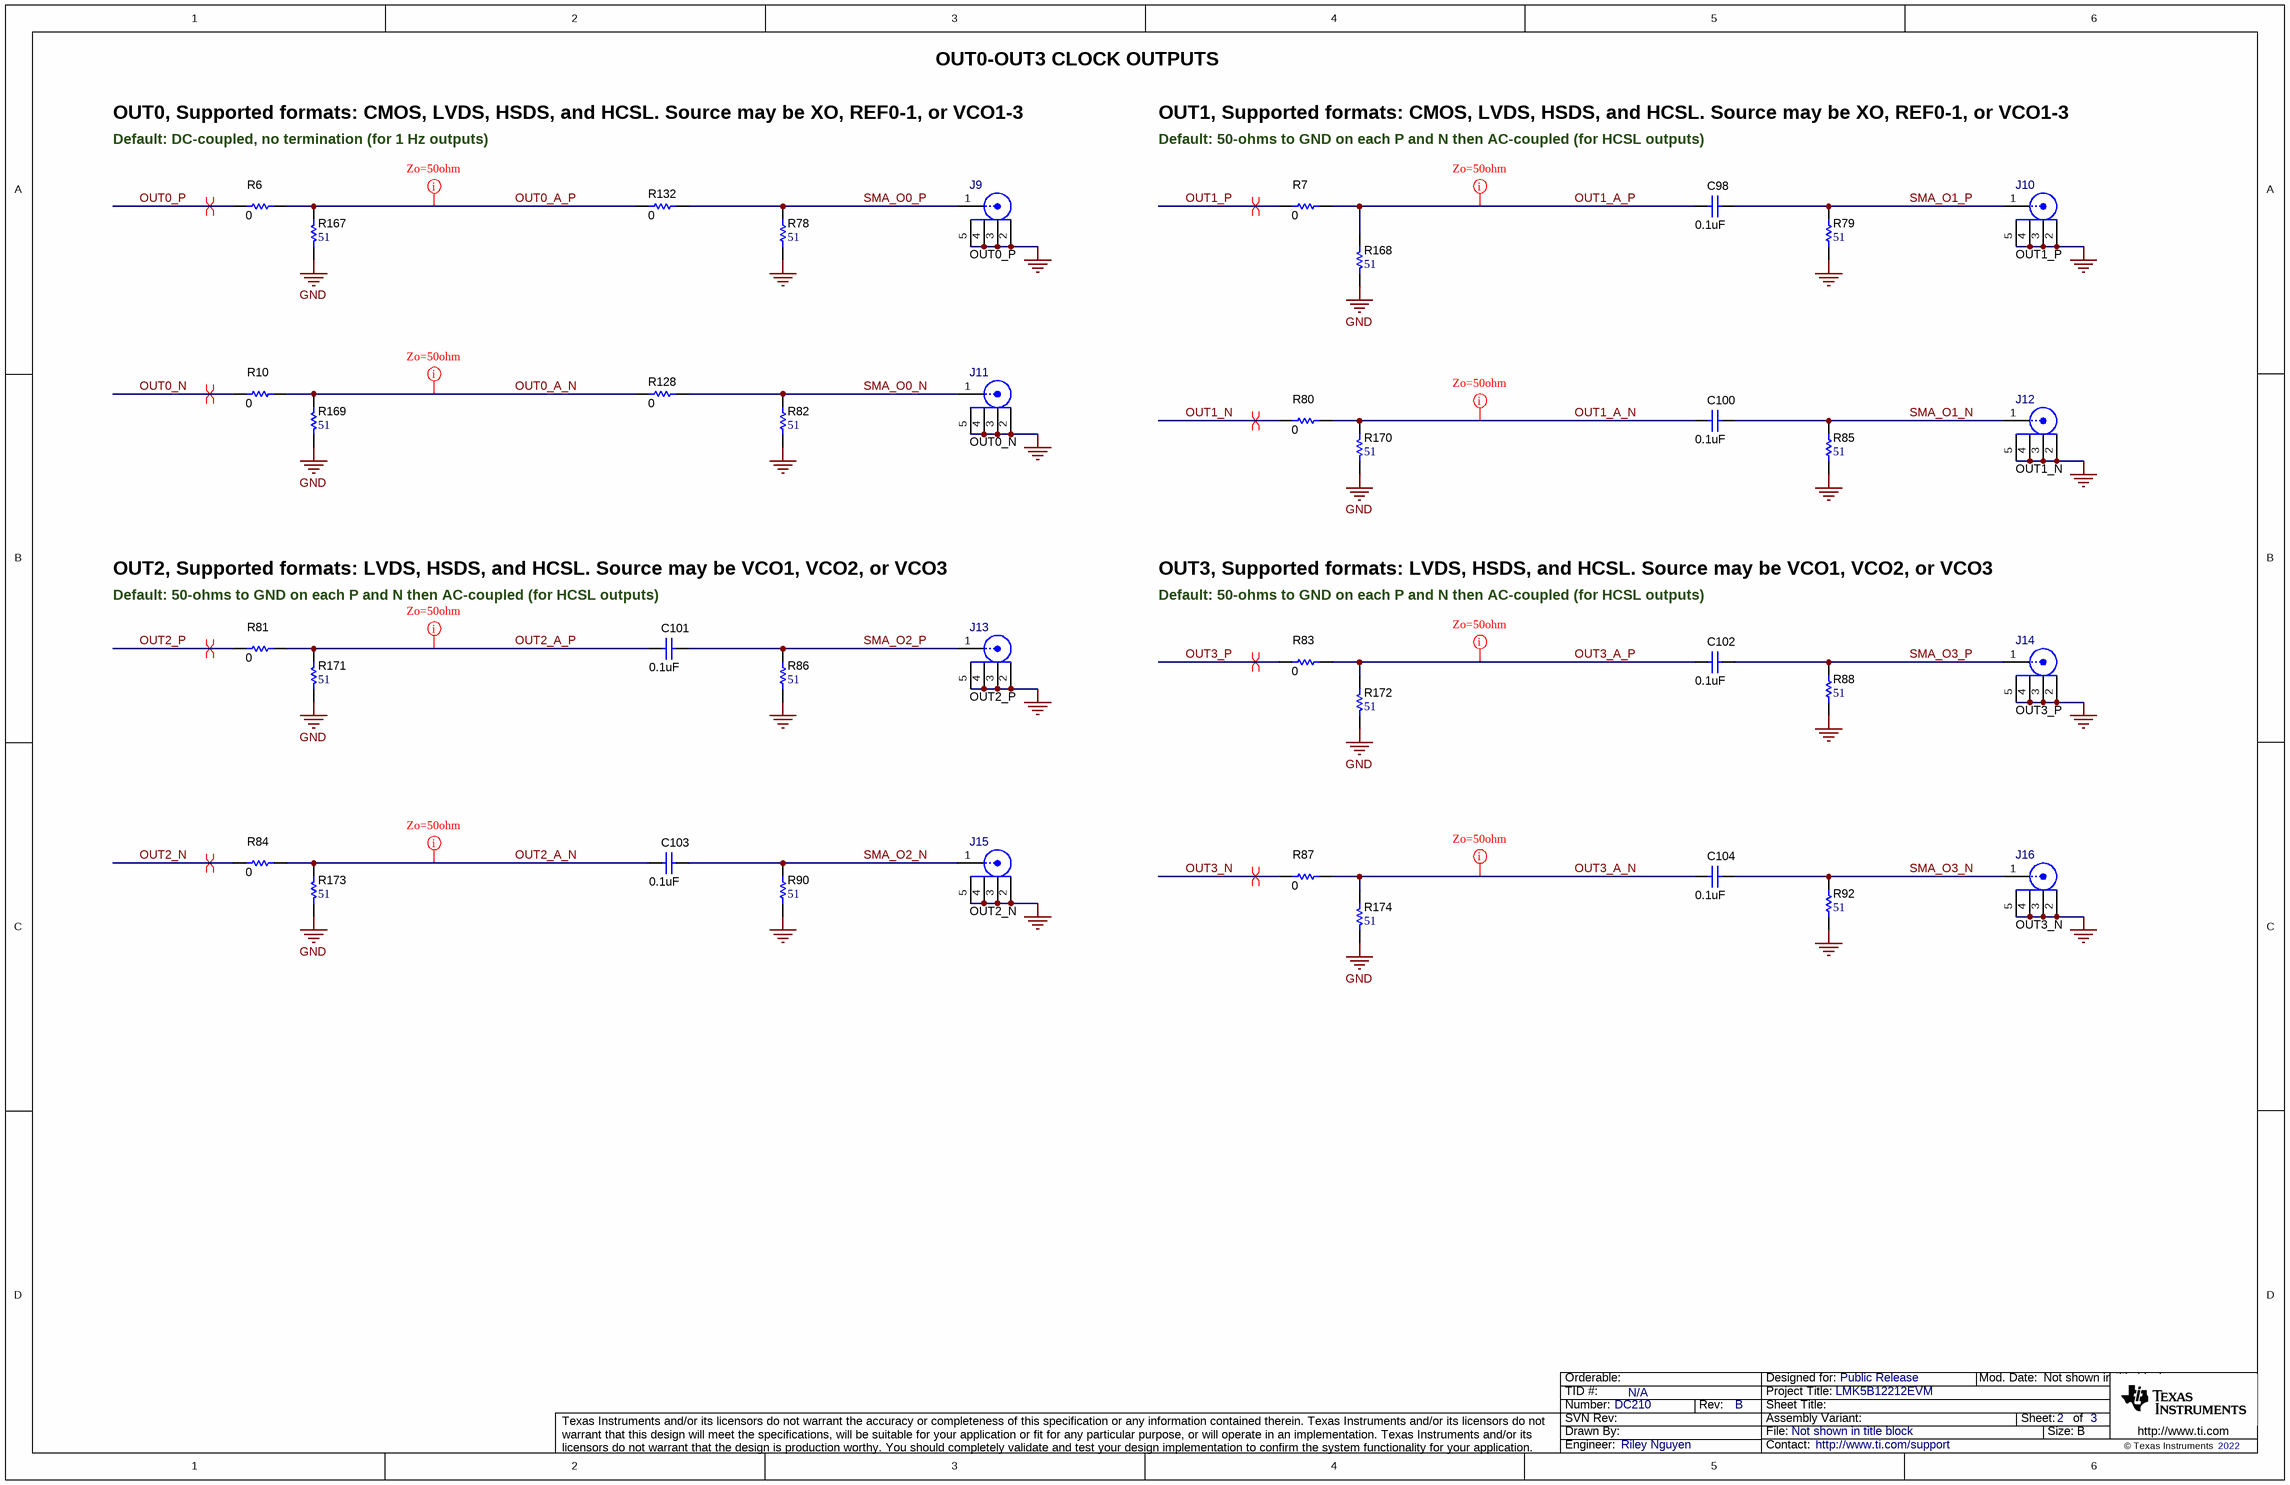
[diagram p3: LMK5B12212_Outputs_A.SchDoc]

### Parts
C98  ValueDisplayed: 0.1uF  [0402L]  (hidden comment: GRM155R71E104KE14D)
C100  ValueDisplayed: 0.1uF  [0402L]  (hidden comment: GRM155R71E104KE14D)
C101  ValueDisplayed: 0.1uF  [0402L]  (hidden comment: GRM155R71E104KE14D)
C102  ValueDisplayed: 0.1uF  [0402L]  (hidden comment: GRM155R71E104KE14D)
C103  ValueDisplayed: 0.1uF  [0402L]  (hidden comment: GRM155R71E104KE14D)
C104  ValueDisplayed: 0.1uF  [0402L]  (hidden comment: GRM155R71E104KE14D)
J9  OUT0_P  [FP-CON-SMA-EDGE-S_CONN_JACK-MFG]
J10  OUT1_P  [FP-CON-SMA-EDGE-S_CONN_JACK-MFG]
J11  OUT0_N  [FP-CON-SMA-EDGE-S_CONN_JACK-MFG]
J12  OUT1_N  [FP-CON-SMA-EDGE-S_CONN_JACK-MFG]
J13  OUT2_P  [FP-CON-SMA-EDGE-S_CONN_JACK-MFG]
J14  OUT3_P  [FP-CON-SMA-EDGE-S_CONN_JACK-MFG]
J15  OUT2_N  [FP-CON-SMA-EDGE-S_CONN_JACK-MFG]
J16  OUT3_N  [FP-CON-SMA-EDGE-S_CONN_JACK-MFG]
R6  ValueDisplayed: 0  [0402L]  (hidden comment: RK73Z1ETTP)
R7  ValueDisplayed: 0  [0402L]  (hidden comment: RK73Z1ETTP)
R10  ValueDisplayed: 0  [0402L]  (hidden comment: RK73Z1ETTP)
R78  ValueDisplayed: 51  [0402L]  (hidden comment: RC0402JR-0751RL)
R79  ValueDisplayed: 51  [0402L]  (hidden comment: RC0402JR-0751RL)
R80  ValueDisplayed: 0  [0402L]  (hidden comment: RK73Z1ETTP)
R81  ValueDisplayed: 0  [0402L]  (hidden comment: RK73Z1ETTP)
R82  ValueDisplayed: 51  [0402L]  (hidden comment: RC0402JR-0751RL)
R83  ValueDisplayed: 0  [0402L]  (hidden comment: RK73Z1ETTP)
R84  ValueDisplayed: 0  [0402L]  (hidden comment: RK73Z1ETTP)
R85  ValueDisplayed: 51  [0402L]  (hidden comment: RC0402JR-0751RL)
R86  ValueDisplayed: 51  [0402L]  (hidden comment: RC0402JR-0751RL)
R87  ValueDisplayed: 0  [0402L]  (hidden comment: RK73Z1ETTP)
R88  ValueDisplayed: 51  [0402L]  (hidden comment: RC0402JR-0751RL)
R90  ValueDisplayed: 51  [0402L]  (hidden comment: RC0402JR-0751RL)
R92  ValueDisplayed: 51  [0402L]  (hidden comment: RC0402JR-0751RL)
R128  ValueDisplayed: 0  [0402L]  (hidden comment: RK73Z1ETTP)
R132  ValueDisplayed: 0  [0402L]  (hidden comment: RK73Z1ETTP)
R167  ValueDisplayed: 51  [0402L]  (hidden comment: RC0402JR-0751RL)
R168  ValueDisplayed: 51  [0402L]  (hidden comment: RC0402JR-0751RL)
R169  ValueDisplayed: 51  [0402L]  (hidden comment: RC0402JR-0751RL)
R170  ValueDisplayed: 51  [0402L]  (hidden comment: RC0402JR-0751RL)
R171  ValueDisplayed: 51  [0402L]  (hidden comment: RC0402JR-0751RL)
R172  ValueDisplayed: 51  [0402L]  (hidden comment: RC0402JR-0751RL)
R173  ValueDisplayed: 51  [0402L]  (hidden comment: RC0402JR-0751RL)
R174  ValueDisplayed: 51  [0402L]  (hidden comment: RC0402JR-0751RL)

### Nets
GND: J9.2 J9.3 J9.4 J9.5 J10.2 J10.3 J10.4 J10.5 J11.2 J11.3 J11.4 J11.5 J12.2 J12.3 J12.4 J12.5 J13.2 J13.3 J13.4 J13.5 J14.2 J14.3 J14.4 J14.5 J15.2 J15.3 J15.4 J15.5 J16.2 J16.3 J16.4 J16.5 R78.1 R79.1 R82.1 R85.1 R86.1 R88.1 R90.1 R92.1 R167.2 R168.2 R169.2 R170.2 R171.2 R172.2 R173.2 R174.2
OUT0_A_N: R10.2 R128.1 R169.1
OUT0_A_P: R6.2 R132.1 R167.1
OUT0_N: R10.1
OUT0_P: R6.1
OUT1_A_N: C100.2 R80.2 R170.1
OUT1_A_P: C98.2 R7.2 R168.1
OUT1_N: R80.1
OUT1_P: R7.1
OUT2_A_N: C103.2 R84.2 R173.1
OUT2_A_P: C101.2 R81.2 R171.1
OUT2_N: R84.1
OUT2_P: R81.1
OUT3_A_N: C104.2 R87.2 R174.1
OUT3_A_P: C102.2 R83.2 R172.1
OUT3_N: R87.1
OUT3_P: R83.1
SMA_O0_N: J11.1 R82.2 R128.2
SMA_O0_P: J9.1 R78.2 R132.2
SMA_O1_N: C100.1 J12.1 R85.2
SMA_O1_P: C98.1 J10.1 R79.2
SMA_O2_N: C103.1 J15.1 R90.2
SMA_O2_P: C101.1 J13.1 R86.2
SMA_O3_N: C104.1 J16.1 R92.2
SMA_O3_P: C102.1 J14.1 R88.2

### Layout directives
rule Impedance Constraint [Min = 45.00    Max = 55.00    ]: OUT0_A_N, OUT0_A_P, OUT1_A_N, OUT1_A_P, OUT2_A_N, OUT2_A_P, OUT3_A_N, OUT3_A_P
differential pair: OUT0_N, OUT0_P, OUT1_N, OUT1_P, OUT2_N, OUT2_P, OUT3_N, OUT3_P

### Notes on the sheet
- OUT0-OUT3 CLOCK OUTPUTS
- OUT0, Supported formats: CMOS, LVDS, HSDS, and HCSL. Source may be XO, REF0-1, or VCO1-3
- Default: DC-coupled, no termination (for 1 Hz outputs)
- OUT1, Supported formats: CMOS, LVDS, HSDS, and HCSL. Source may be XO, REF0-1, or VCO1-3
- Default: 50-ohms to GND on each P and N then AC-coupled (for HCSL outputs)
- OUT2, Supported formats: LVDS, HSDS, and HCSL. Source may be VCO1, VCO2, or VCO3
- OUT3, Supported formats: LVDS, HSDS, and HCSL. Source may be VCO1, VCO2, or VCO3

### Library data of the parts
C98 C100-C104 = CMP-0006659-2: CAP, CERM, 0.1 uF, 25 V, +/- 10%, X7R, 0402; Manufacturer: MuRata; TaMin_C: -55°C; Polarized: N; SizeAreaWB_mm2: 3; Value1: Unknown; U/M: EA; Value: 0.1uF; TaMax_C: 125°C; SizeZ_mm: 0.6; SizeX_mm: 1; SizeY_mm: 0.5; Cap_Case: 0402; Value2: 25V; CompType: Capacitor; Cap_F: 100nF; AEC Category: Q200
J9-J16 = CMP-0088000-4: as J4 on sheet LMK5B12212_DUT
R6 R7 R10 R80 R81 R83 R84 R87 = CMP-0027007-2: RES, 0, 5%, 0.063 W, AEC-Q200 Grade 0, 0402; Manufacturer: KOA Speer; Power_W: 63mW; TempCo: ppm/C; Value_Code: 0000; U/M: EA; Value: 0; EIA_Code: E24; SizeX_mm: 1; SizeY_mm: 0.5; SizeZ_mm: 0.6; Value2: 0.063W; CompType: Resistor; AEC Qualified: Y; AEC Category: Q200
R78 R79 R82 R85 R86 R88 R90 R92 = CMP-0027006-2: RES, 51, 5%, 0.0625 W, 0402; Manufacturer: Yageo America; Value: 51; Value_Code: 51R0; Power_W: 62.5mW; VDC_V: 50V; TempCo: 100 ppm/C; EIA_Code: E24; SizeArea_mm2: 0.5; SizeX_mm: 1; SizeZ_mm: 0.6; AEC Category: Q200; AEC Qualified: N; U/M: EA
R128 = CMP-0027007-2: RES, 0, 5%, 0.063 W, AEC-Q200 Grade 0, 0402; Manufacturer: KOA Speer; TempCo: ppm/C; U/M: EA; Value: 0; SizeZ_mm: 0.6; SizeX_mm: 1; SizeY_mm: 0.5; Value2: 0.063W; CompType: Resistor; AEC Qualified: Y; AEC Category: Q200; Power_W: 63mW; Value_Code: 0000; EIA_Code: E24
R132 = CMP-0027007-2: RES, 0, 5%, 0.063 W, AEC-Q200 Grade 0, 0402; Manufacturer: KOA Speer; TempCo: ppm/C; U/M: EA; Value: 0; SizeZ_mm: 0.6; SizeX_mm: 1; SizeY_mm: 0.5; Value2: 0.063W; AEC Qualified: Y; AEC Category: Q200; Power_W: 63mW; Value_Code: 0000; EIA_Code: E24
R167-R174 = CMP-0027006-2: RES, 51, 5%, 0.0625 W, 0402; Manufacturer: Yageo America; Power_W: 62.5mW; TempCo: 100 ppm/C; Value_Code: 51R0; Value: 51; EIA_Code: E24; SizeX_mm: 1; SizeY_mm: 0.5; SizeZ_mm: 0.6; AEC Qualified: N; VDC_V: 50V; AEC Category: Q200; U/M: EA

## Sheet LMK5B12212_Outputs_B.SchDoc
size 431 x 279 mm; Date: Not shown in title block; ApprovedBy: Not shown in title block; CheckedBy: Not shown in title block; Author: Not shown in title block; CompanyName: Not shown in title block; Engineer: Not shown in title block; Organization: Not shown in title block; Address1: Not shown in title block; Address2: Not shown in title block; Address3: Not shown in title block; Address4: Not shown in title block; DocumentNumber: 2; Revision: Use project parameter SCH_Rev; SheetNumber: 2; SheetTotal: 3; PageSetup: Record=PageOptions¦CenterHorizontal=True¦CenterVertical=True¦PrintScale=1.00¦XCorrection=1.00¦YCorrection=1.00¦PrintKind=0¦BorderSize=5000000¦LeftOffset=0¦BottomOffset=0¦Orientation=2¦PaperLength=1000¦PaperWidth=1000¦Scale=100¦PaperSource=15¦PrintQuality=600¦MediaType=1¦DitherType=10¦PaperKind=Letter¦PrintScaleMode=1
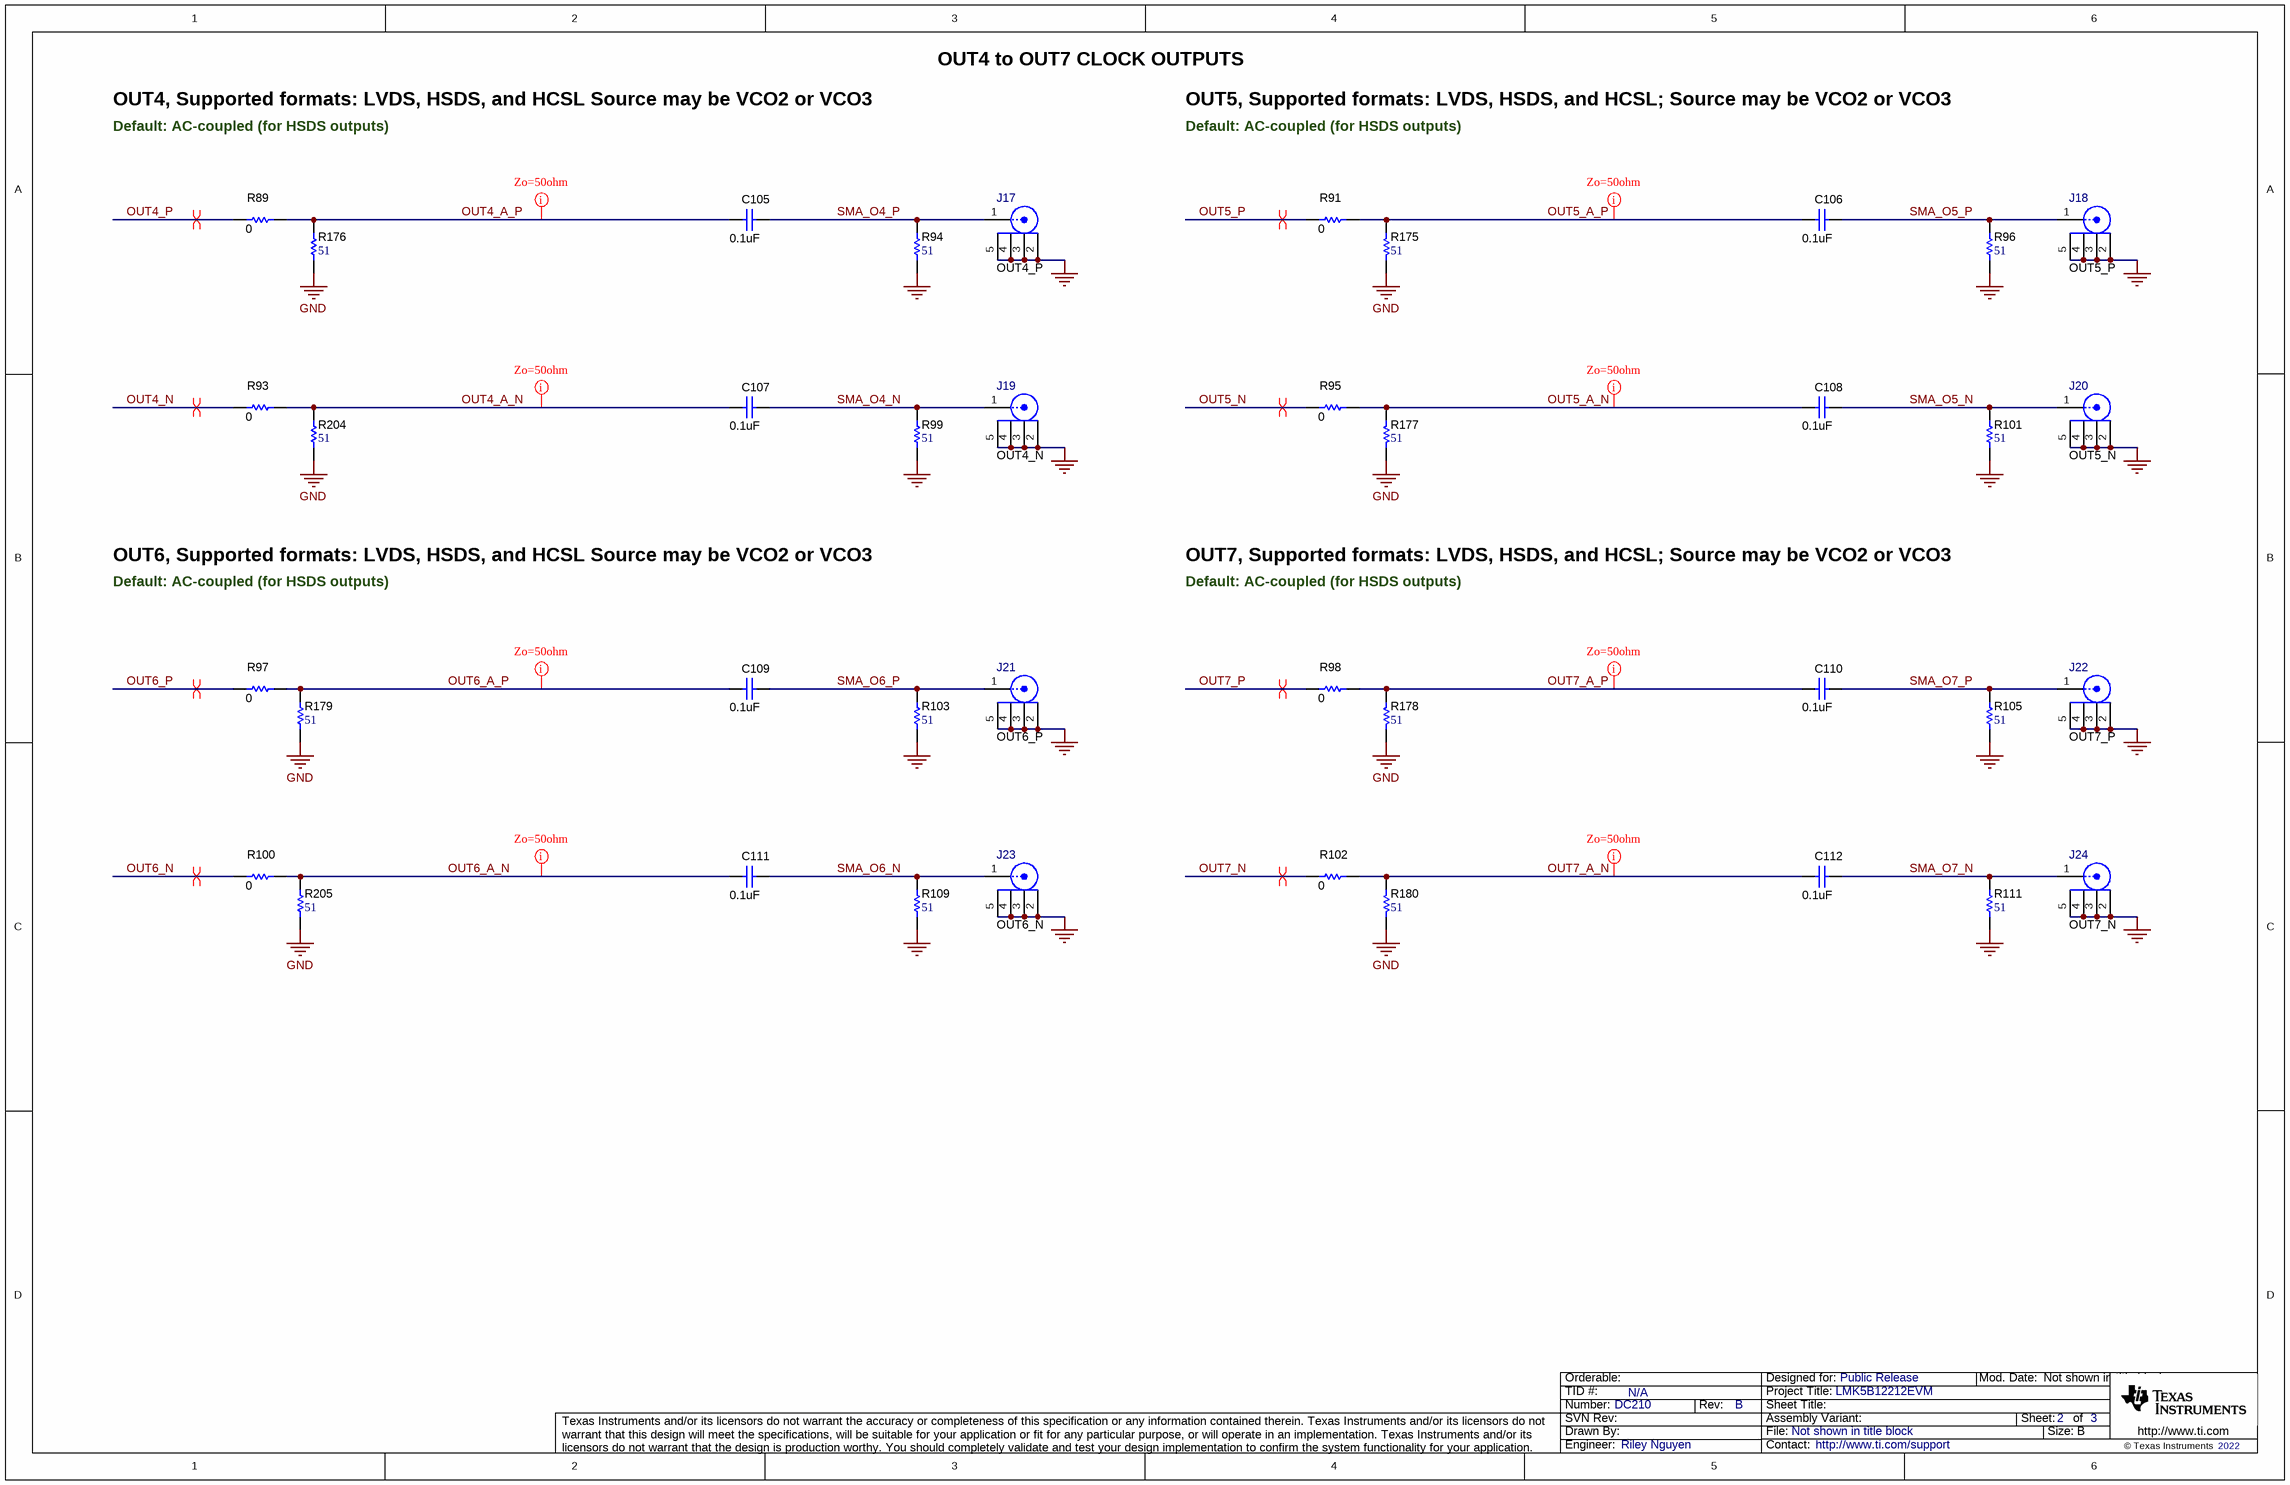
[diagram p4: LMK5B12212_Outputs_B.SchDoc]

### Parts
C105  ValueDisplayed: 0.1uF  [0402L]  (hidden comment: GRM155R71E104KE14D)
C106  ValueDisplayed: 0.1uF  [0402L]  (hidden comment: GRM155R71E104KE14D)
C107  ValueDisplayed: 0.1uF  [0402L]  (hidden comment: GRM155R71E104KE14D)
C108  ValueDisplayed: 0.1uF  [0402L]  (hidden comment: GRM155R71E104KE14D)
C109  ValueDisplayed: 0.1uF  [0402L]  (hidden comment: GRM155R71E104KE14D)
C110  ValueDisplayed: 0.1uF  [0402L]  (hidden comment: GRM155R71E104KE14D)
C111  ValueDisplayed: 0.1uF  [0402L]  (hidden comment: GRM155R71E104KE14D)
C112  ValueDisplayed: 0.1uF  [0402L]  (hidden comment: GRM155R71E104KE14D)
J17  OUT4_P  [FP-CON-SMA-EDGE-S_CONN_JACK-MFG]
J18  OUT5_P  [FP-CON-SMA-EDGE-S_CONN_JACK-MFG]
J19  OUT4_N  [FP-CON-SMA-EDGE-S_CONN_JACK-MFG]
J20  OUT5_N  [FP-CON-SMA-EDGE-S_CONN_JACK-MFG]
J21  OUT6_P  [FP-CON-SMA-EDGE-S_CONN_JACK-MFG]
J22  OUT7_P  [FP-CON-SMA-EDGE-S_CONN_JACK-MFG]
J23  OUT6_N  [FP-CON-SMA-EDGE-S_CONN_JACK-MFG]
J24  OUT7_N  [FP-CON-SMA-EDGE-S_CONN_JACK-MFG]
R89  ValueDisplayed: 0  [0402L]  (hidden comment: RK73Z1ETTP)
R91  ValueDisplayed: 0  [0402L]  (hidden comment: RK73Z1ETTP)
R93  ValueDisplayed: 0  [0402L]  (hidden comment: RK73Z1ETTP)
R94  ValueDisplayed: 51  [0402L]  (hidden comment: RC0402JR-0751RL)
R95  ValueDisplayed: 0  [0402L]  (hidden comment: RK73Z1ETTP)
R96  ValueDisplayed: 51  [0402L]  (hidden comment: RC0402JR-0751RL)
R97  ValueDisplayed: 0  [0402L]  (hidden comment: RK73Z1ETTP)
R98  ValueDisplayed: 0  [0402L]  (hidden comment: RK73Z1ETTP)
R99  ValueDisplayed: 51  [0402L]  (hidden comment: RC0402JR-0751RL)
R100  ValueDisplayed: 0  [0402L]  (hidden comment: RK73Z1ETTP)
R101  ValueDisplayed: 51  [0402L]  (hidden comment: RC0402JR-0751RL)
R102  ValueDisplayed: 0  [0402L]  (hidden comment: RK73Z1ETTP)
R103  ValueDisplayed: 51  [0402L]  (hidden comment: RC0402JR-0751RL)
R105  ValueDisplayed: 51  [0402L]  (hidden comment: RC0402JR-0751RL)
R109  ValueDisplayed: 51  [0402L]  (hidden comment: RC0402JR-0751RL)
R111  ValueDisplayed: 51  [0402L]  (hidden comment: RC0402JR-0751RL)
R175  ValueDisplayed: 51  [0402L]  (hidden comment: RC0402JR-0751RL)
R176  ValueDisplayed: 51  [0402L]  (hidden comment: RC0402JR-0751RL)
R177  ValueDisplayed: 51  [0402L]  (hidden comment: RC0402JR-0751RL)
R178  ValueDisplayed: 51  [0402L]  (hidden comment: RC0402JR-0751RL)
R179  ValueDisplayed: 51  [0402L]  (hidden comment: RC0402JR-0751RL)
R180  ValueDisplayed: 51  [0402L]  (hidden comment: RC0402JR-0751RL)
R204  ValueDisplayed: 51  [0402L]  (hidden comment: RC0402JR-0751RL)
R205  ValueDisplayed: 51  [0402L]  (hidden comment: RC0402JR-0751RL)

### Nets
GND: J17.2 J17.3 J17.4 J17.5 J18.2 J18.3 J18.4 J18.5 J19.2 J19.3 J19.4 J19.5 J20.2 J20.3 J20.4 J20.5 J21.2 J21.3 J21.4 J21.5 J22.2 J22.3 J22.4 J22.5 J23.2 J23.3 J23.4 J23.5 J24.2 J24.3 J24.4 J24.5 R94.1 R96.1 R99.1 R101.1 R103.1 R105.1 R109.1 R111.1 R175.2 R176.2 R177.2 R178.2 R179.2 R180.2 R204.2 R205.2
OUT4_A_N: C107.2 R93.2 R204.1
OUT4_A_P: C105.2 R89.2 R176.1
OUT4_N: R93.1
OUT4_P: R89.1
OUT5_A_N: C108.2 R95.2 R177.1
OUT5_A_P: C106.2 R91.2 R175.1
OUT5_N: R95.1
OUT5_P: R91.1
OUT6_A_N: C111.2 R100.2 R205.1
OUT6_A_P: C109.2 R97.2 R179.1
OUT6_N: R100.1
OUT6_P: R97.1
OUT7_A_N: C112.2 R102.2 R180.1
OUT7_A_P: C110.2 R98.2 R178.1
OUT7_N: R102.1
OUT7_P: R98.1
SMA_O4_N: C107.1 J19.1 R99.2
SMA_O4_P: C105.1 J17.1 R94.2
SMA_O5_N: C108.1 J20.1 R101.2
SMA_O5_P: C106.1 J18.1 R96.2
SMA_O6_N: C111.1 J23.1 R109.2
SMA_O6_P: C109.1 J21.1 R103.2
SMA_O7_N: C112.1 J24.1 R111.2
SMA_O7_P: C110.1 J22.1 R105.2

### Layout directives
rule Impedance Constraint [Min = 45.00    Max = 55.00    ]: OUT4_A_N, OUT4_A_P, OUT5_A_N, OUT5_A_P, OUT6_A_N, OUT6_A_P, OUT7_A_N, OUT7_A_P
differential pair: OUT4_N, OUT4_P, OUT5_N, OUT5_P, OUT6_N, OUT6_P, OUT7_N, OUT7_P

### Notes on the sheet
- OUT4, Supported formats: LVDS, HSDS, and HCSL Source may be VCO2 or VCO3
- OUT4 to OUT7 CLOCK OUTPUTS
- OUT5, Supported formats: LVDS, HSDS, and HCSL; Source may be VCO2 or VCO3
- Default: AC-coupled (for HSDS outputs)
- OUT6, Supported formats: LVDS, HSDS, and HCSL Source may be VCO2 or VCO3
- OUT7, Supported formats: LVDS, HSDS, and HCSL; Source may be VCO2 or VCO3

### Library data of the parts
C105-C112 = CMP-0006659-2: as C98 on sheet LMK5B12212_Outputs_A
J17-J24 = CMP-0088000-4: as J4 on sheet LMK5B12212_DUT
R89 R91 R93 R95 R97 R98 R100 R102 = CMP-0027007-2: as R6 on sheet LMK5B12212_Outputs_A
R94 R96 R99 R101 R103 R105 R109 R111 = CMP-0027006-2: as R78 on sheet LMK5B12212_Outputs_A
R175-R180 R204 R205 = CMP-0027006-2: as R167 on sheet LMK5B12212_Outputs_A

## Sheet LMK5B12212_Outputs_C.SchDoc
size 431 x 279 mm; Date: Not shown in title block; ApprovedBy: Not shown in title block; CheckedBy: Not shown in title block; Author: Not shown in title block; CompanyName: Not shown in title block; Engineer: Not shown in title block; Organization: Not shown in title block; Address1: Not shown in title block; Address2: Not shown in title block; Address3: Not shown in title block; Address4: Not shown in title block; DocumentNumber: 2; Revision: Use project parameter SCH_Rev; SheetNumber: 2; SheetTotal: 3; PageSetup: Record=PageOptions¦CenterHorizontal=True¦CenterVertical=True¦PrintScale=1.00¦XCorrection=1.00¦YCorrection=1.00¦PrintKind=0¦BorderSize=5000000¦LeftOffset=0¦BottomOffset=0¦Orientation=2¦PaperLength=1000¦PaperWidth=1000¦Scale=100¦PaperSource=15¦PrintQuality=600¦MediaType=1¦DitherType=10¦PaperKind=Letter¦PrintScaleMode=1
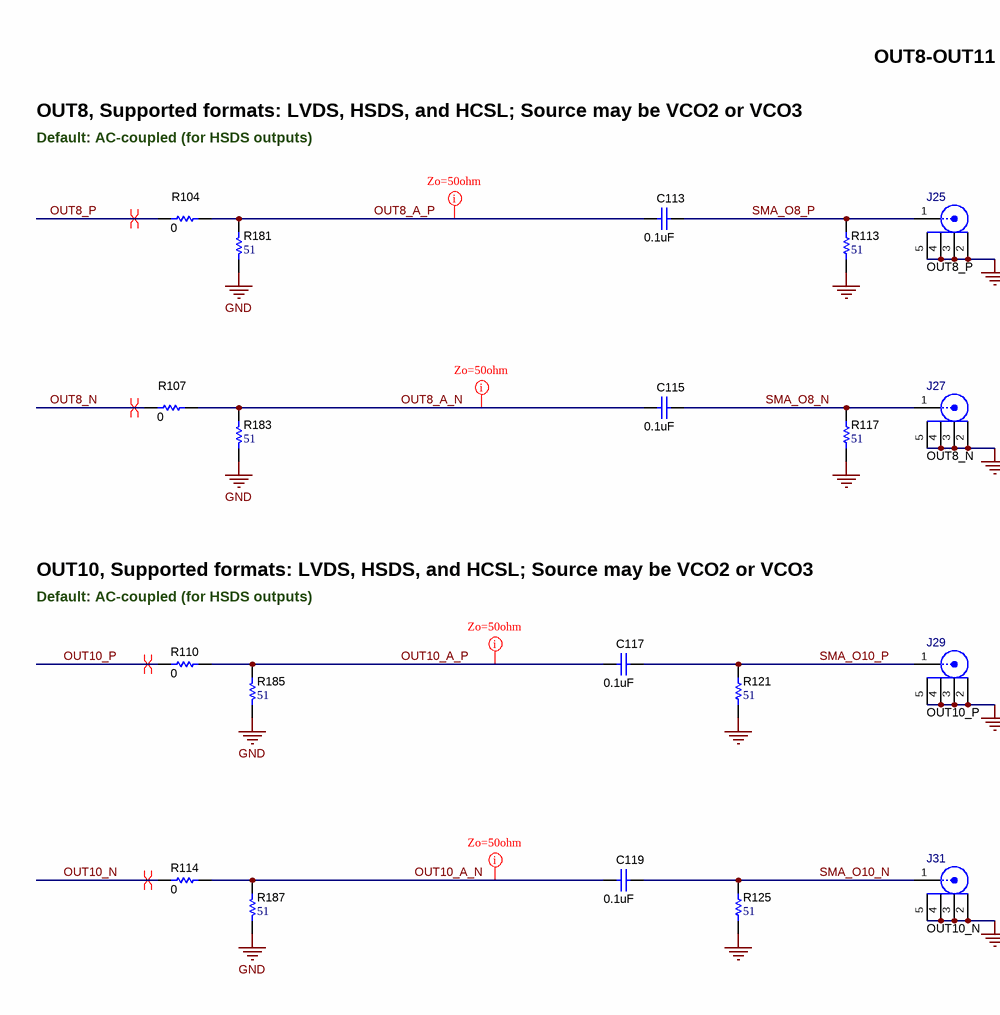
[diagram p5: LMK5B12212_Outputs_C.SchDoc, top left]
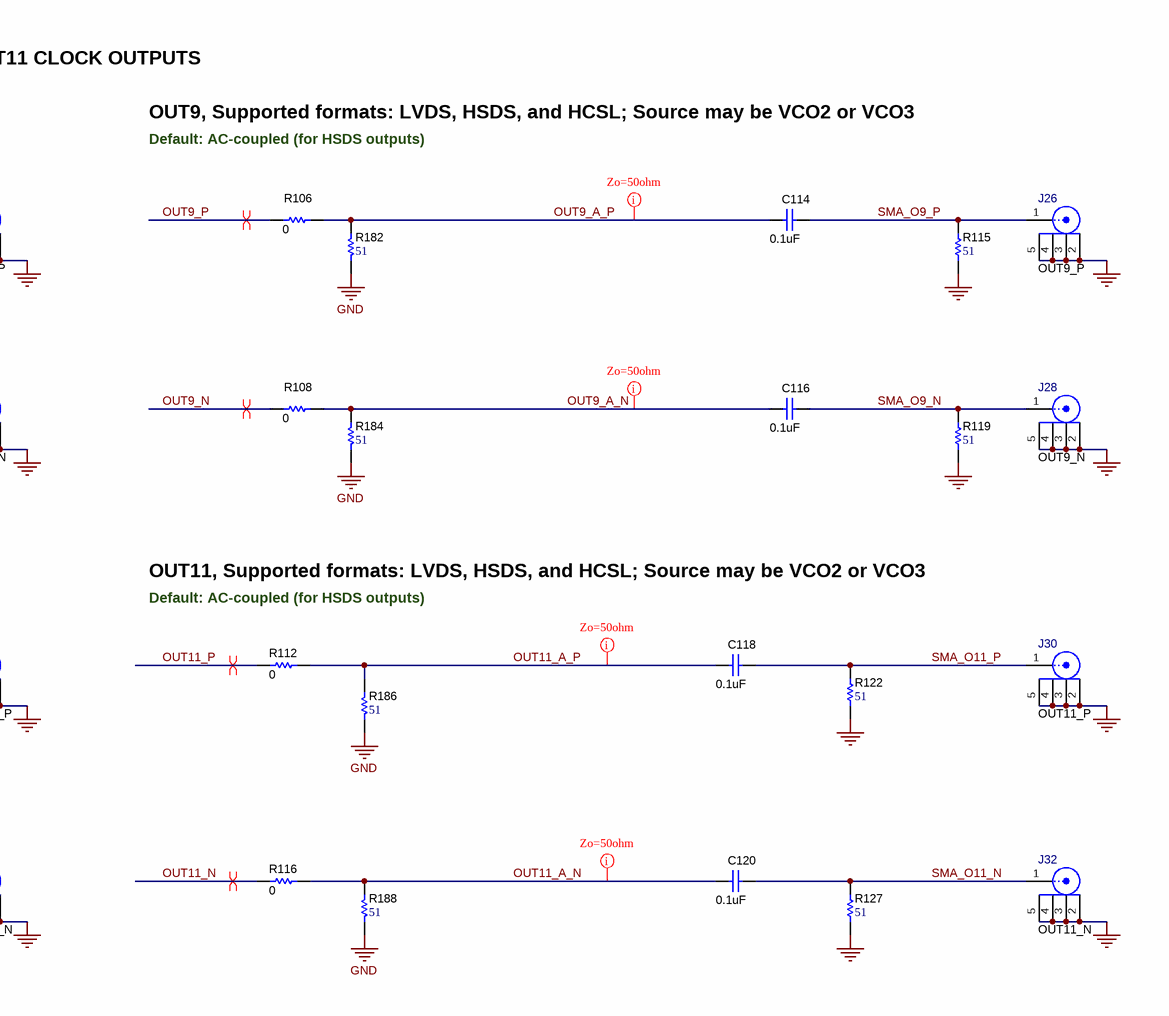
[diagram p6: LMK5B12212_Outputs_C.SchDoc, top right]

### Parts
C113  ValueDisplayed: 0.1uF  [0402L]  (hidden comment: GRM155R71E104KE14D)
C114  ValueDisplayed: 0.1uF  [0402L]  (hidden comment: GRM155R71E104KE14D)
C115  ValueDisplayed: 0.1uF  [0402L]  (hidden comment: GRM155R71E104KE14D)
C116  ValueDisplayed: 0.1uF  [0402L]  (hidden comment: GRM155R71E104KE14D)
C117  ValueDisplayed: 0.1uF  [0402L]  (hidden comment: GRM155R71E104KE14D)
C118  ValueDisplayed: 0.1uF  [0402L]  (hidden comment: GRM155R71E104KE14D)
C119  ValueDisplayed: 0.1uF  [0402L]  (hidden comment: GRM155R71E104KE14D)
C120  ValueDisplayed: 0.1uF  [0402L]  (hidden comment: GRM155R71E104KE14D)
J25  OUT8_P  [FP-CON-SMA-EDGE-S_CONN_JACK-MFG]
J26  OUT9_P  [FP-CON-SMA-EDGE-S_CONN_JACK-MFG]
J27  OUT8_N  [FP-CON-SMA-EDGE-S_CONN_JACK-MFG]
J28  OUT9_N  [FP-CON-SMA-EDGE-S_CONN_JACK-MFG]
J29  OUT10_P  [FP-CON-SMA-EDGE-S_CONN_JACK-MFG]
J30  OUT11_P  [FP-CON-SMA-EDGE-S_CONN_JACK-MFG]
J31  OUT10_N  [FP-CON-SMA-EDGE-S_CONN_JACK-MFG]
J32  OUT11_N  [FP-CON-SMA-EDGE-S_CONN_JACK-MFG]
R104  ValueDisplayed: 0  [0402L]  (hidden comment: RK73Z1ETTP)
R106  ValueDisplayed: 0  [0402L]  (hidden comment: RK73Z1ETTP)
R107  ValueDisplayed: 0  [0402L]  (hidden comment: RK73Z1ETTP)
R108  ValueDisplayed: 0  [0402L]  (hidden comment: RK73Z1ETTP)
R110  ValueDisplayed: 0  [0402L]  (hidden comment: RK73Z1ETTP)
R112  ValueDisplayed: 0  [0402L]  (hidden comment: RK73Z1ETTP)
R113  ValueDisplayed: 51  [0402L]  (hidden comment: RC0402JR-0751RL)
R114  ValueDisplayed: 0  [0402L]  (hidden comment: RK73Z1ETTP)
R115  ValueDisplayed: 51  [0402L]  (hidden comment: RC0402JR-0751RL)
R116  ValueDisplayed: 0  [0402L]  (hidden comment: RK73Z1ETTP)
R117  ValueDisplayed: 51  [0402L]  (hidden comment: RC0402JR-0751RL)
R119  ValueDisplayed: 51  [0402L]  (hidden comment: RC0402JR-0751RL)
R121  ValueDisplayed: 51  [0402L]  (hidden comment: RC0402JR-0751RL)
R122  ValueDisplayed: 51  [0402L]  (hidden comment: RC0402JR-0751RL)
R125  ValueDisplayed: 51  [0402L]  (hidden comment: RC0402JR-0751RL)
R127  ValueDisplayed: 51  [0402L]  (hidden comment: RC0402JR-0751RL)
R181  ValueDisplayed: 51  [0402L]  (hidden comment: RC0402JR-0751RL)
R182  ValueDisplayed: 51  [0402L]  (hidden comment: RC0402JR-0751RL)
R183  ValueDisplayed: 51  [0402L]  (hidden comment: RC0402JR-0751RL)
R184  ValueDisplayed: 51  [0402L]  (hidden comment: RC0402JR-0751RL)
R185  ValueDisplayed: 51  [0402L]  (hidden comment: RC0402JR-0751RL)
R186  ValueDisplayed: 51  [0402L]  (hidden comment: RC0402JR-0751RL)
R187  ValueDisplayed: 51  [0402L]  (hidden comment: RC0402JR-0751RL)
R188  ValueDisplayed: 51  [0402L]  (hidden comment: RC0402JR-0751RL)

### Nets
GND: J25.2 J25.3 J25.4 J25.5 J26.2 J26.3 J26.4 J26.5 J27.2 J27.3 J27.4 J27.5 J28.2 J28.3 J28.4 J28.5 J29.2 J29.3 J29.4 J29.5 J30.2 J30.3 J30.4 J30.5 J31.2 J31.3 J31.4 J31.5 J32.2 J32.3 J32.4 J32.5 R113.1 R115.1 R117.1 R119.1 R121.1 R122.1 R125.1 R127.1 R181.2 R182.2 R183.2 R184.2 R185.2 R186.2 R187.2 R188.2
OUT8_A_N: C115.2 R107.2 R183.1
OUT8_A_P: C113.2 R104.2 R181.1
OUT8_N: R107.1
OUT8_P: R104.1
OUT9_A_N: C116.2 R108.2 R184.1
OUT9_A_P: C114.2 R106.2 R182.1
OUT9_N: R108.1
OUT9_P: R106.1
OUT10_A_N: C119.2 R114.2 R187.1
OUT10_A_P: C117.2 R110.2 R185.1
OUT10_N: R114.1
OUT10_P: R110.1
OUT11_A_N: C120.2 R116.2 R188.1
OUT11_A_P: C118.2 R112.2 R186.1
OUT11_N: R116.1
OUT11_P: R112.1
SMA_O8_N: C115.1 J27.1 R117.2
SMA_O8_P: C113.1 J25.1 R113.2
SMA_O9_N: C116.1 J28.1 R119.2
SMA_O9_P: C114.1 J26.1 R115.2
SMA_O10_N: C119.1 J31.1 R125.2
SMA_O10_P: C117.1 J29.1 R121.2
SMA_O11_N: C120.1 J32.1 R127.2
SMA_O11_P: C118.1 J30.1 R122.2

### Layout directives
rule Impedance Constraint [Min = 45.00    Max = 55.00    ]: OUT8_A_N, OUT8_A_P, OUT9_A_N, OUT9_A_P, OUT10_A_N, OUT10_A_P, OUT11_A_N, OUT11_A_P
differential pair: OUT8_N, OUT8_P, OUT9_N, OUT9_P, OUT10_N, OUT10_P, OUT11_N, OUT11_P

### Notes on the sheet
- OUT8-OUT11 CLOCK OUTPUTS
- OUT8, Supported formats: LVDS, HSDS, and HCSL; Source may be VCO2 or VCO3
- Default: AC-coupled (for HSDS outputs)
- OUT9, Supported formats: LVDS, HSDS, and HCSL; Source may be VCO2 or VCO3
- OUT10, Supported formats: LVDS, HSDS, and HCSL; Source may be VCO2 or VCO3
- OUT11, Supported formats: LVDS, HSDS, and HCSL; Source may be VCO2 or VCO3

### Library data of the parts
C113-C120 = CMP-0006659-2: as C98 on sheet LMK5B12212_Outputs_A
J25-J32 = CMP-0088000-4: as J4 on sheet LMK5B12212_DUT
R104 R106-R108 R110 R112 R114 R116 = CMP-0027007-2: as R6 on sheet LMK5B12212_Outputs_A
R113 R115 R117 R119 R121 R122 R125 R127 = CMP-0027006-2: as R78 on sheet LMK5B12212_Outputs_A
R181-R188 = CMP-0027006-2: as R167 on sheet LMK5B12212_Outputs_A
